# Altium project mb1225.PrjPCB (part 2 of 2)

## Sheet USB_OTG_HS.SchDoc: USB OTG HS PHY with micro A-B connector
size A4; Date: 29-OCT-2015; Author: A.B; CompanyName: STMicroelectronics; Organization: MCD/TOOLS/GNB; Address1: 12, Rue Jules HOROWITZ; Address2: 38019 Grenoble; Address3: FRANCE; DocumentNumber: MB1225; Revision: B-01; SheetNumber: 9; SheetTotal: 13; Project: STM32F769I-DISCO
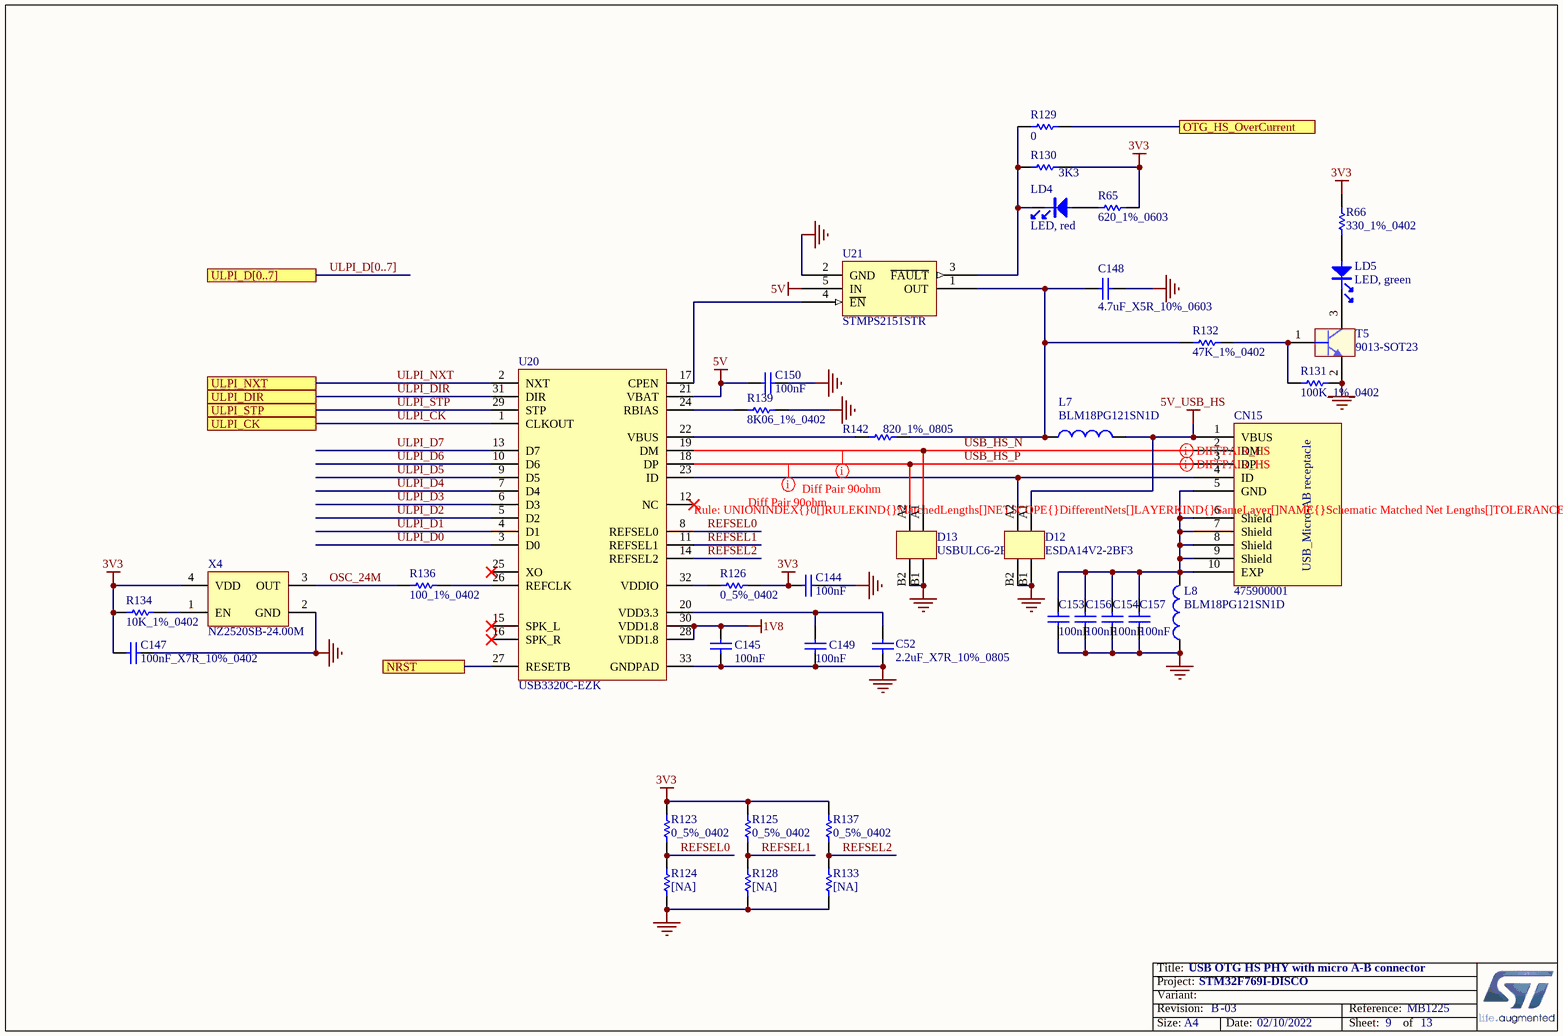
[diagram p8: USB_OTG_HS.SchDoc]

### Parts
C52  2.2uF_X7R_10%_0805  [TAN-A]
C144  100nF  [0402C]
C145  100nF  [0402C]
C147  100nF_X7R_10%_0402  [0402C]
C148  4.7uF_X5R_10%_0603  [0603C]
C149  100nF  [0402C]
C150  100nF  [0402C]
C153  100nF  [0402C]
C154  100nF  [0402C]
C156  100nF  [0402C]
C157  100nF  [0402C]
CN15  475900001  [MOLEX_47590001]
D12  ESDA14V2-2BF3  [BGA4_0R4_0R8X0R8]
D13  USBULC6-2F3  [BGA4_0R4_0R8X0R8]
L7  BLM18PG121SN1D  [0603L]
L8  BLM18PG121SN1D  [0603L]
LD4  LED, red  [0603D]
LD5  LED, green  [0603D]
R65  620_1%_0603  [0603R]
R66  330_1%_0402  [0402R]
R123  0_5%_0402  [0402R]
R124  [NA]  [0402R]
R125  0_5%_0402  [0402R]
R126  0_5%_0402  [0402R]
R128  [NA]  [0402R]
R129  0  [0402R]
R130  3K3  [0402R]
R131  100K_1%_0402  [0402R]
R132  47K_1%_0402  [0402R]
R133  [NA]  [0402R]
R134  10K_1%_0402  [0402R]
R136  100_1%_0402  [0402R]
R137  0_5%_0402  [0402R]
R139  8K06_1%_0402  [0402R]
R142  820_1%_0805  [0805R]
T5  9013-SOT23  [SOT-23]
U20  USB3320C-EZK  [QFN32_0R5_5X5]
U21  STMPS2151STR  [SOT23-5]
X4  NZ2520SB-24.00M  [OSC_4SM_2R5X2]

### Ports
NRST, OTG_HS_OverCurrent, ULPI_CK, ULPI_D[0..7], ULPI_DIR, ULPI_NXT, ULPI_STP

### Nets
1V8: C145.2 U20.28(VDD1.8) U20.30(VDD1.8)
3V3: C144.1 C147.1 R65.2 R66.2 R123.2 R125.2 R126.2 R130.1 R134.1 R137.2 X4.4(VDD)
5V: C150.1 U20.21(VBAT) U21.5(IN)
5V_USB_HS: CN15.1(VBUS) D12.A1 L7.2
GND: C52.1 C144.2 C145.1 C147.2 C148.2 C149.1 C150.2 C153.1 C154.1 C156.1 C157.1 D12.B1 D12.B2 D13.B1 D13.B2 L8.1 R124.1 R128.1 R131.2 R133.1 R139.2 T5.2(E) U20.33(GNDPAD) U21.2(GND) X4.2(GND)  [project net POE7]
NRST: U20.27(RESETB) ; port NRST
OSC_24M: R136.1 X4.3(OUT)
OTG_HS_OverCurrent: R129.2 ; port OTG_HS_OverCurrent
REFSEL0: R123.1 R124.2 U20.8(REFSEL0)
REFSEL1: R125.1 R128.2 U20.11(REFSEL1)
REFSEL2: R133.2 R137.1 U20.14(REFSEL2)
ULPI_CK: U20.1(CLKOUT) ; port ULPI_CK  [project net PA5]
ULPI_D0: U20.3(D0)  [project net PA3]
ULPI_D1: U20.4(D1)  [project net PB0]
ULPI_D2: U20.5(D2)  [project net PB1]
ULPI_D3: U20.6(D3)  [project net PB10]
ULPI_D4: U20.7(D4)  [project net PB11]
ULPI_D5: U20.9(D5)  [project net PB12]
ULPI_D6: U20.10(D6)  [project net PB13]
ULPI_D7: U20.13(D7)  [project net PB5]
ULPI_DIR: U20.31(DIR) ; port ULPI_DIR  [project net PI11]
ULPI_NXT: U20.2(NXT) ; port ULPI_NXT  [project net PH4]
ULPI_STP: U20.29(STP) ; port ULPI_STP  [project net PC0]
USB_HS_N: CN15.2(DM) D13.A1 U20.19(DM)
USB_HS_P: CN15.3(DP) D13.A2 U20.18(DP)
NetC52_2: C52.2 C149.2 U20.20(VDD3.3)
NetC148_1: C148.1 L7.1 R132.1 R142.2 U21.1(OUT)
NetC153_2: C153.2 C154.2 C156.2 C157.2 CN15.5(GND) CN15.6(Shield) CN15.7(Shield) CN15.8(Shield) CN15.9(Shield) CN15.10(EXP) L8.2
NetCN15_4: CN15.4(ID) D12.A2 U20.23(ID)
NetLD4_1: LD4.1 R65.1
NetLD4_2: LD4.2 R129.1 R130.2 U21.3(~{FAULT})
NetLD5_1: LD5.1 R66.1
NetLD5_2: LD5.2 T5.3(C)
NetR126_1: R126.1 U20.32(VDDIO)
NetR131_1: R131.1 R132.2 T5.1(B)
NetR134_2: R134.2 X4.1(EN)
NetR136_2: R136.2 U20.26(REFCLK)
NetR139_1: R139.1 U20.24(RBIAS)
NetR142_1: R142.1 U20.22(VBUS)
NetU20_17: U20.17(CPEN) U21.4(~{EN})

Not connected (* = marked no-connect by the designer): U20 12(NC)* 15(SPK_L)* 16(SPK_R)* 25(XO)*

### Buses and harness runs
bus ULPI_D[0..7] = port ULPI_D[0..7]

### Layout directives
differential pair: USB_HS_N, USB_HS_P
rule Matched Net Lengths [Tolerance = 150mil]: USB_HS_N, USB_HS_P

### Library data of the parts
C52 = Cap_2.2uF_X7R_10%_0805: Capacitor,2.2uF,16V, X7R,10%,0805,YAGEO; Manuf_Part_1: CC0805KKX7R7BB225
C144 C145 C147 C149 C150 C153 C154 C156 C157 = Cap_100nF_X7R_10%_0402: Capacitor,100nF,16V,X7R,10%,0402,YAGEO; Manuf_Part_1: CC0402KRX7R7BB104
C148 = Cap_4.7uF_X5R_10%_0603: Capacitor,4.7uF,16V, X5R,10%,0603,YAGEO; Manuf_Part_1: CC0603KRX5R7BB475; Order: CC0603KRX5R7BB105
CN15 = 475900001: USB-MICRO-AB, 47590-0001, SMT, MOLEX
D12 = ESDA14V2-2BF3: Quad bidirectional Transil array for ESD protection; Manuf_1: STM; ECCN_US/EU: EAR99/NEC; Provided: ST; Ref St: 9179040
D13 = USBULC6-2F3: 2-line Transil, (TVS), ultralow capacitance protection for high speed USB; Manuf_1: STM; ECCN_US/EU: EAR99/NEC; Ref St: 9151090; Provided: ST
L7 L8 = BEAD_120R_2A_0603: Bead,120R,2A,0603,BLM18PG121SN1D,MURATA; Manuf_Part_3: FCM1608KF-601T03; Manuf_2: TDK; Manuf_Part_2: MPZ1608S300A; Manuf_3: Tai-tech; Value: 100uH; Description_3: Bead,600R,350mA,0603,FCM1608KF-601T03,Tai-tech; Description_2: Bead,30R,5A,0603,MPZ1608S300A,TDK
LD4 = LED_red: LED, red, 0603; Manuf_1: everlight; Manuf_Part_1: 19-213-R6C-AP1Q2B/3T; ECCN_US/EU: EAR99/NEC
LD5 = LED_green: LED, green, 0603; Manuf_1: everlight; Manuf_Part_1: 19-213SYGC/S530-E2/TR8; ECCN_US/EU: EAR99/NEC
R65 = Res_620_1%_0603: Resistor,620,0603,1%,VISHAY; Manuf_Part_1: CRCW0603620RFKEA; Manuf_1: VISHAY DRALORIC; Value: 620; Order: 2122341
R66 = Res_330_1%_0402: Resistor,330,0402,1%,YAGEO; Manuf_Part_1: RC0402FR-07330RL; Value: 330
R123 R125 R126 R137 = Res_0_5%_0402: Resistor,0,0402,5%,YAGEO; Manuf_Part_1: RC0402JR-070RL; Value: 0; Order: 2363467
R124 R128 R133 = Res_NA_0402: Resistor,[NA],0402; Fitted: NO
R129 = Res_0_5%_0402: Resistor,0,0402,5%,YAGEO; Manuf_Part_1: RC0402JR-070RL; Order: 2363467
R130 = Res_3K3_1%_0402: Resistor,3K3,0402,1%,YAGEO; Manuf_Part_1: RC0402FR-073K3L
R131 = Res_100K_1%_0402: Resistor,100K,0402,1%,YAGEO; Manuf_Part_1: RC0402FR-07100KL; Manuf_Part_2: RT0402FRE07100KL
R132 = Res_47K_1%_0402: Resistor,47K,0402,1%,YAGEO; Manuf_Part_1: RC0402FR-0747KL; Order: 9239430
R134 = Res_10K_1%_0402: Resistor,10K,0402,1%,YAGEO; Manuf_Part_1: RC0402FR-0710KL
R136 = Res_100_1%_0402: Resistor,100,0402,1%,YAGEO; Manuf_Part_1: RC0402FR-07100RL; Value: 100; Order: 9239111
R139 = Res_8K06_1%_0402: Resistor,8K06,0402,1%,YAGEO; Manuf_Part_1: RC0402FR-078K06L
R142 = Res_820_1%_0805: Resistor,820,0805,1%,YAGEO; Manuf_Part_1: RC0805FR-07820RL; Value: 820
T5 = 9013-SOT23: NPN Bipolar Transistor; Manuf_1: NXP; Manuf_Part_1: BSR14; Order: 1081310; ECCN_US/EU: EAR99/NEC
U20 = USB3320C-EZK: USB3320C,  Hi-Speed USB Host, Device or OTG PHY with ULPI Low Pin Interface; Manuf_1: MICROCHIP; Manuf_Part_1: USB3320C-EZK-TR; ECCN_US/EU: EAR99/NEC; Provided: Sub Co
U21 = STMPS2151STR: Enhanced single channel power switches; Manuf_1: STM; Provided: ST; ECCN_US/EU: EAR99/NEC; Ref St: xxxxxx
X4 = OSC_24M_NZ2520SB: Oscillator 24.00Mhz, -+50PPM, 3.3V, Temp -55 to +125°C; Manuf_Part_2: KC2520B24.0000C10E00; Manuf_1: NDK; Manuf_Part_1: NZ2520SB 24MHz END4869A; Manuf_2: AVX Corp/Kyocera Corp; ECCN_US/EU: EAR99/NEC; Ref St: 9157032; Provided: ST

## Sheet STM32F7.SchDoc: STM32F769NIH6 Connexion
size A3; Date: 29-OCT-2015; Author: A.B; CompanyName: STMicroelectronics; Organization: MCD/TOOLS/GNB; Address1: 12, Rue Jules HOROWITZ; Address2: 38019 Grenoble; Address3: FRANCE; DocumentNumber: MB1225; Revision: B-01; SheetNumber: 4; SheetTotal: 13; Project: STM32F769I-DISCO
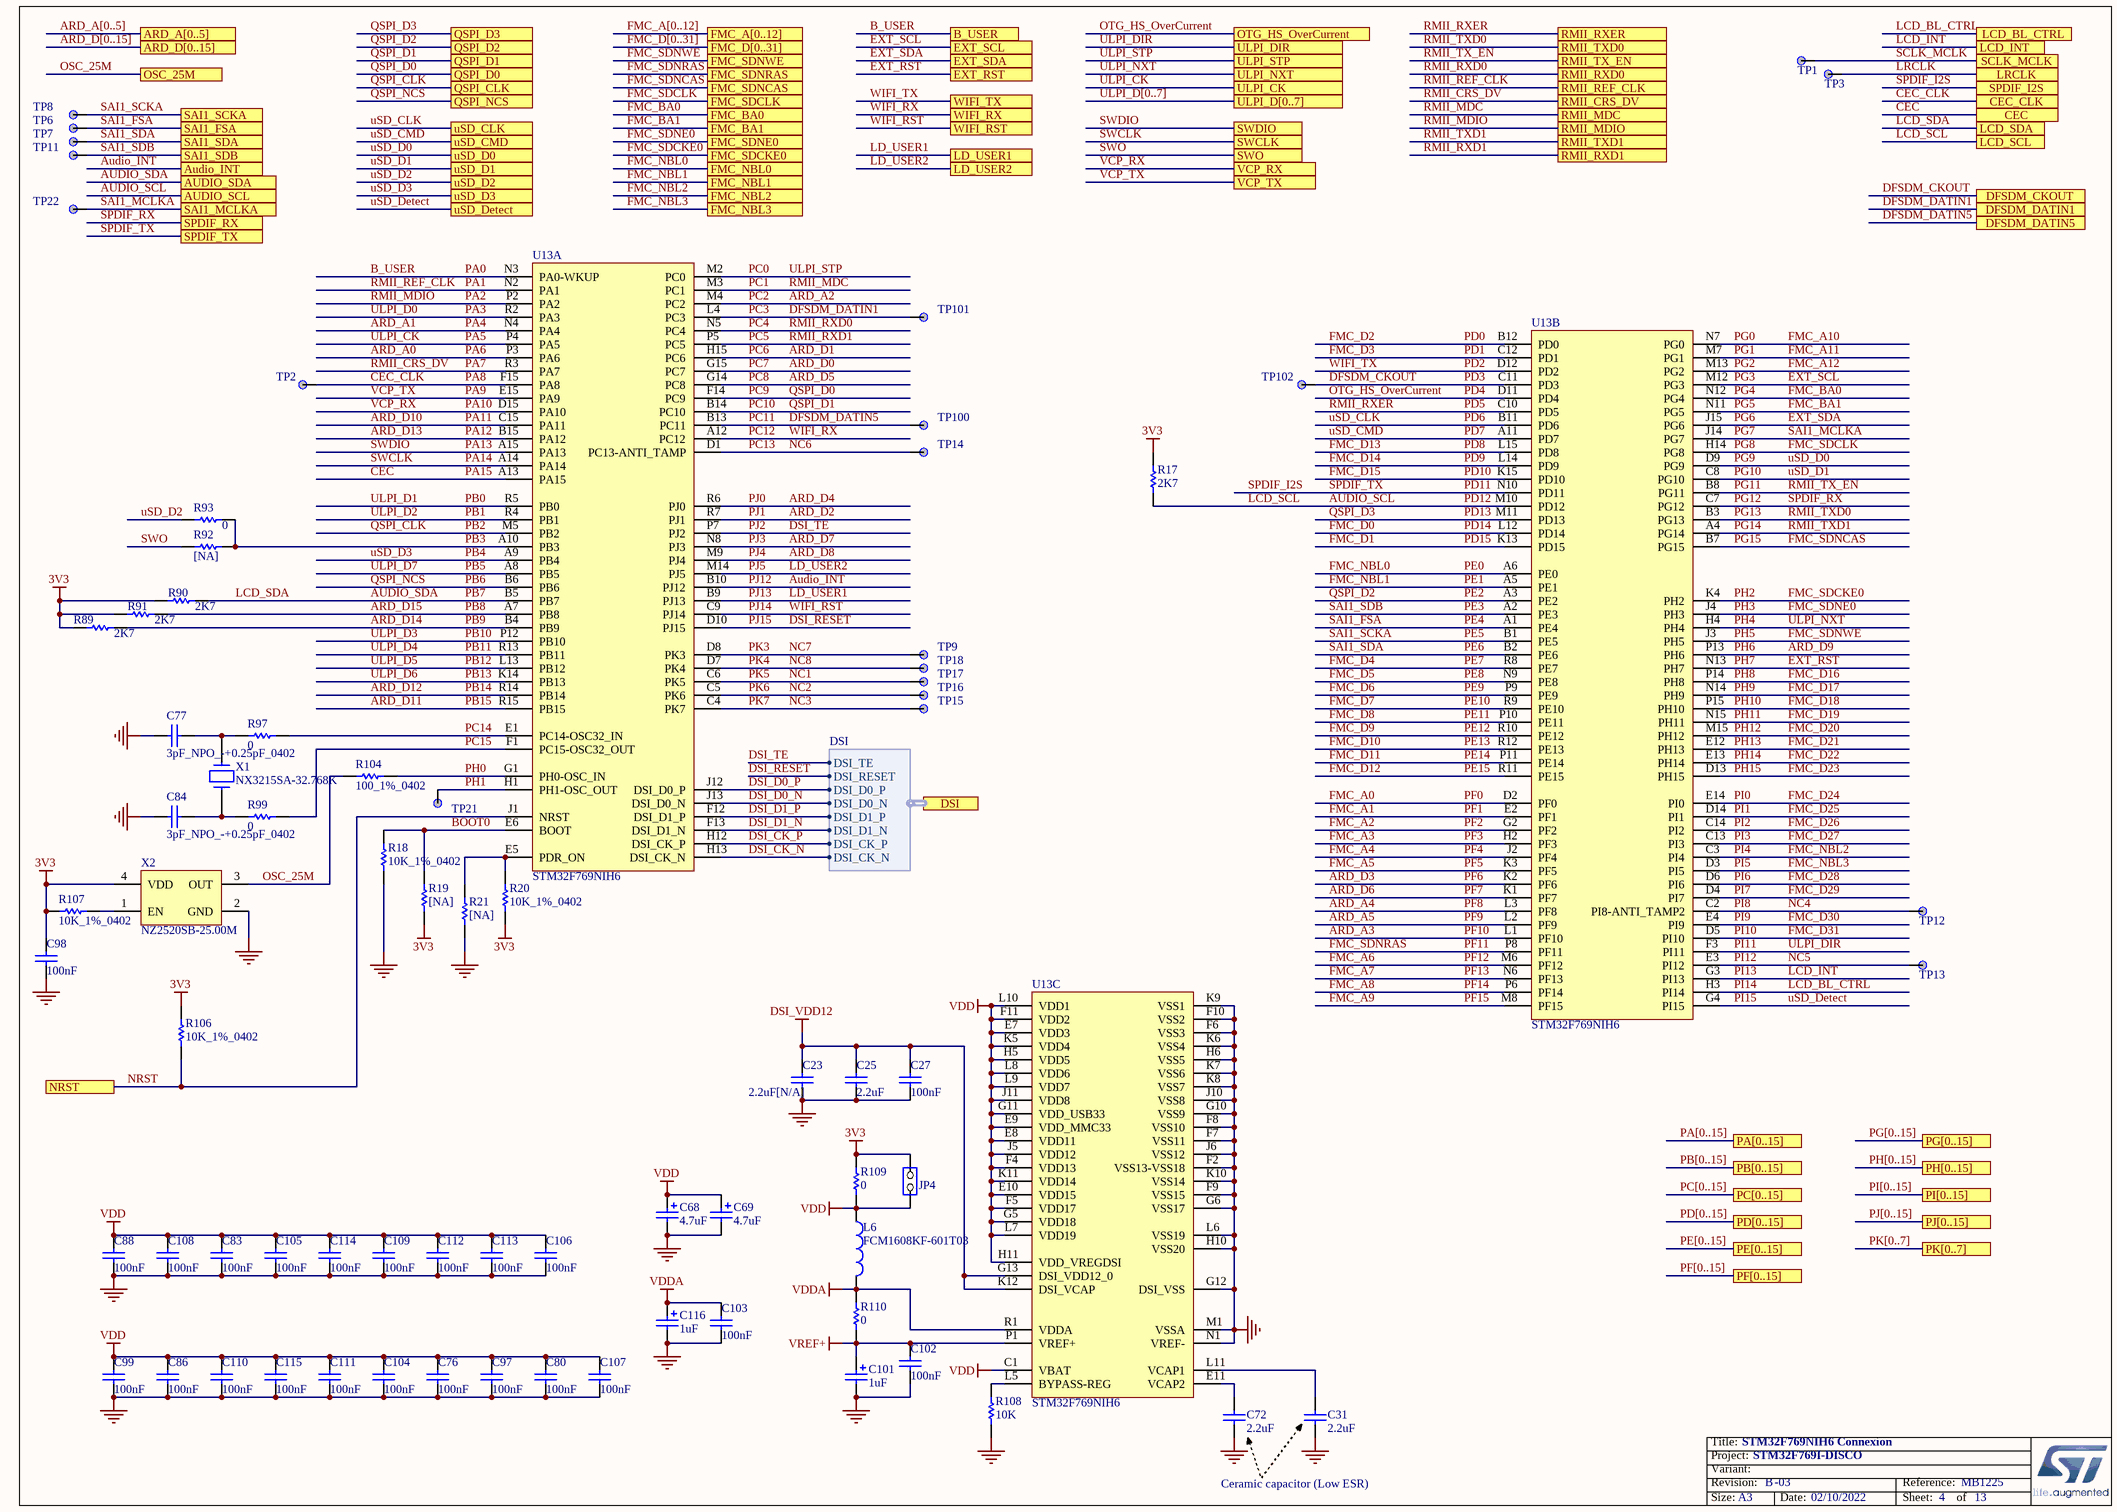
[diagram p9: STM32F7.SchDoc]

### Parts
C23  2.2uF[N/A]  [1206C]
C25  2.2uF  [0603C]
C27  100nF  [0402C]
C31  2.2uF  [1206C]
C68  4.7uF  [TAN-A]
C69  4.7uF  [TAN-A]
C72  2.2uF  [1206C]
C76  100nF  [0402C]
C77  3pF_NPO_-+0.25pF_0402  [0402C]
C80  100nF  [0402C]
C83  100nF  [0402C]
C84  3pF_NPO_-+0.25pF_0402  [0402C]
C86  100nF  [0402C]
C88  100nF  [0402C]
C97  100nF  [0402C]
C98  100nF  [0402C]
C99  100nF  [0402C]
C101  1uF  [TAN-A]
C102  100nF  [0402C]
C103  100nF  [0402C]
C104  100nF  [0402C]
C105  100nF  [0402C]
C106  100nF  [0402C]
C107  100nF  [0402C]
C108  100nF  [0402C]
C109  100nF  [0402C]
C110  100nF  [0402C]
C111  100nF  [0402C]
C112  100nF  [0402C]
C113  100nF  [0402C]
C114  100nF  [0402C]
C115  100nF  [0402C]
C116  1uF  [TAN-A]
JP4  JP2  [SIP2]  (value not drawn)
L6  FCM1608KF-601T03  [0603L]
R17  2K7  [0402R]
R18  10K_1%_0402  [0402R]
R19  [NA]  [0402R]
R20  10K_1%_0402  [0402R]
R21  [NA]  [0402R]
R89  2K7  [0402R]
R90  2K7  [0402R]
R91  2K7  [0402R]
R92  [NA]  [0402R]
R93  0  [0402R]
R97  0  [0402R]
R99  0  [0402R]
R104  100_1%_0402  [0402R]
R106  10K_1%_0402  [0402R]
R107  10K_1%_0402  [0402R]
R108  10K  [0402R]
R109  0  [0603R-GS]
R110  0  [0603R-GS]
TP1  TP  [TP_C40]  (value not drawn)
TP2  TP  [TP_C40]  (value not drawn)
TP3  TP  [TP_C40]  (value not drawn)
TP6  TP  [TP_C40]  (value not drawn)
TP7  TP  [TP_C40]  (value not drawn)
TP8  TP  [TP_C40]  (value not drawn)
TP9  TP  [TP_C40]  (value not drawn)
TP11  TP  [TP_C40]  (value not drawn)
TP12  TP  [TP_C40]  (value not drawn)
TP13  TP  [TP_C40]  (value not drawn)
TP14  TP  [TP_C40]  (value not drawn)
TP15  TP  [TP_C40]  (value not drawn)
TP16  TP  [TP_C40]  (value not drawn)
TP17  TP  [TP_C40]  (value not drawn)
TP18  TP  [TP_C40]  (value not drawn)
TP21  TP  [TP_C40]  (value not drawn)
TP22  TP  [TP_C40]  (value not drawn)
TP100  TP  [TP_C40]  (value not drawn)
TP101  TP  [TP_C40]  (value not drawn)
TP102  TP  [TP_C40]  (value not drawn)
U13  STM32F769NIH6  [BGA216_0R8_13X13]  (parts A,B,C of 3)
X1  NX3215SA-32.768K  [XTAL_2SM_3R2X1R5]
X2  NZ2520SB-25.00M  [OSC_4SM_2R5X2]

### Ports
ARD_A[0..5], ARD_D[0..15], Audio_INT, AUDIO_SCL, AUDIO_SDA, B_USER, CEC, CEC_CLK, DFSDM_CKOUT, DFSDM_DATIN1, DFSDM_DATIN5, DSI (harness DSI), EXT_RST, EXT_SCL, EXT_SDA, FMC_A[0..12], FMC_BA0, FMC_BA1, FMC_D[0..31], FMC_NBL0, FMC_NBL1, FMC_NBL2, FMC_NBL3, FMC_SDCKE0, FMC_SDCLK, FMC_SDNCAS, FMC_SDNE0, FMC_SDNRAS, FMC_SDNWE, LCD_BL_CTRL, LCD_INT, LCD_SCL, LCD_SDA, LD_USER1, LD_USER2, LRCLK, NRST, OSC_25M, OTG_HS_OverCurrent, PA[0..15], PB[0..15], PC[0..15], PD[0..15], PE[0..15], PF[0..15], PG[0..15], PH[0..15], PI[0..15], PJ[0..15], PK[0..7], QSPI_CLK, QSPI_D0, QSPI_D1, QSPI_D2, QSPI_D3, QSPI_NCS, RMII_CRS_DV, RMII_MDC, RMII_MDIO, RMII_REF_CLK, RMII_RXD0, RMII_RXD1, RMII_RXER, RMII_TX_EN, RMII_TXD0, RMII_TXD1, SAI1_FSA, SAI1_MCLKA, SAI1_SCKA, SAI1_SDA, SAI1_SDB, SCLK_MCLK, SPDIF_I2S, SPDIF_RX, SPDIF_TX, SWCLK, SWDIO, SWO, ULPI_CK, ULPI_D[0..7], ULPI_DIR, ULPI_NXT, ULPI_STP, uSD_CLK, uSD_CMD, uSD_D0, uSD_D1, uSD_D2, uSD_D3, uSD_Detect, VCP_RX, VCP_TX, WIFI_RST, WIFI_RX, WIFI_TX

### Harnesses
DSI: DSI_CK_P, DSI_CK_N, DSI_D0_P, DSI_D0_N, DSI_D1_P, DSI_D1_N, DSI_TE, DSI_RESET

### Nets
3V3: C98.2 JP4.2(NO) R17.2 R19.1 R20.1 R89.1 R90.1 R91.1 R106.2 R107.1 R109.2 X2.4(VDD)
DSI_VDD12: C23.2 C25.2 C27.2 U13.G13(DSI_VDD12_0) U13.K12(DSI_VCAP)
GND: C23.1 C25.1 C27.1 C31.1 C68.2 C69.2 C72.1 C76.1 C77.1 C80.1 C83.1 C84.1 C86.1 C88.1 C97.1 C98.1 C99.1 C101.2 C102.1 C103.1 C104.1 C105.1 C106.1 C107.1 C108.1 C109.1 C110.1 C111.1 C112.1 C113.1 C114.1 C115.1 C116.2 R18.1 R21.1 R108.1 U13.F2(VSS13-VSS18) U13.F6(VSS3) U13.F7(VSS11) U13.F8(VSS10) U13.F9(VSS15) U13.F10(VSS2) U13.G6(VSS17) U13.G10(VSS9) U13.G12(DSI_VSS) U13.H6(VSS5) U13.H10(VSS20) U13.J6(VSS12) U13.J10(VSS8) U13.K6(VSS4) U13.K7(VSS6) U13.K8(VSS7) U13.K9(VSS1) U13.K10(VSS14) U13.L6(VSS19) U13.M1(VSSA) U13.N1(VREF-) X2.2(GND)  [project net POE7]
VDD: C68.1 C69.1 C76.2 C80.2 C83.2 C86.2 C88.2 C97.2 C99.2 C104.2 C105.2 C106.2 C107.2 C108.2 C109.2 C110.2 C111.2 C112.2 C113.2 C114.2 C115.2 JP4.1(COMMON) L6.1 R109.1 U13.C1(VBAT) U13.E7(VDD3) U13.E8(VDD11) U13.E9(VDD_MMC33) U13.E10(VDD15) U13.F4(VDD13) U13.F5(VDD17) U13.F11(VDD2) U13.G5(VDD18) U13.G11(VDD_USB33) U13.H5(VDD5) U13.H11(VDD_VREGDSI) U13.J5(VDD12) U13.J11(VDD8) U13.K5(VDD4) U13.K11(VDD14) U13.L7(VDD19) U13.L8(VDD6) U13.L9(VDD7) U13.L10(VDD1)
VDDA: C103.2 C116.1 L6.2 R110.1 U13.R1(VDDA)
VREF+: C101.1 C102.2 R110.2 U13.P1(VREF+)
ARD_A0: U13.P3(PA6)  [also labelled PA6]
ARD_A1: U13.N4(PA4)  [also labelled PA4]
ARD_A2: U13.M4(PC2)  [also labelled PC2]
ARD_A3: U13.L1(PF10)  [also labelled PF10]
ARD_A4: U13.L3(PF8)  [also labelled PF8]
ARD_A5: U13.L2(PF9)  [also labelled PF9]
ARD_D0: U13.G15(PC7)  [also labelled PC7]
ARD_D1: U13.H15(PC6)  [also labelled PC6]
ARD_D2: U13.R7(PJ1)  [also labelled PJ1]
ARD_D3: U13.K2(PF6)  [also labelled PF6]
ARD_D4: U13.R6(PJ0)  [also labelled PJ0]
ARD_D5: U13.G14(PC8)  [also labelled PC8]
ARD_D6: U13.K1(PF7)  [also labelled PF7]
ARD_D7: U13.N8(PJ3)  [also labelled PJ3]
ARD_D8: U13.M9(PJ4)  [also labelled PJ4]
ARD_D9: U13.P13(PH6)  [also labelled PH6]
ARD_D10: U13.C15(PA11)  [also labelled PA11]
ARD_D11: U13.R15(PB15)  [also labelled PB15]
ARD_D12: U13.R14(PB14)  [also labelled PB14]
ARD_D13: U13.B15(PA12)  [also labelled PA12]
ARD_D14: R89.2 U13.B4(PB9)  [also labelled PB9]
ARD_D15: R91.2 U13.A7(PB8)  [also labelled PB8]
Audio_INT: U13.B10(PJ12) ; port Audio_INT  [also labelled PJ12]
AUDIO_SCL: R17.1 U13.M10(PD12) ; port AUDIO_SCL, port LCD_SCL  [also labelled LCD_SCL, PD12]
AUDIO_SDA: R90.2 U13.B5(PB7) ; port AUDIO_SDA, port LCD_SDA  [also labelled LCD_SDA, PB7]
B_USER: U13.N3(PA0-WKUP) ; port B_USER  [also labelled PA0]
BOOT0: R18.2 R19.2 U13.E6(BOOT)
CEC: U13.A13(PA15) ; port CEC  [also labelled PA15]
CEC_CLK: TP2.1 U13.F15(PA8) ; port CEC_CLK  [also labelled PA8]
DFSDM_CKOUT: TP102.1 U13.C11(PD3) ; port DFSDM_CKOUT  [also labelled PD3]
DFSDM_DATIN1: TP101.1 U13.L4(PC3) ; port DFSDM_DATIN1  [also labelled PC3]
DFSDM_DATIN5: TP100.1 U13.B13(PC11) ; port DFSDM_DATIN5  [also labelled PC11]
DSI_CK_N: U13.H13(DSI_CK_N) ; port DSI.DSI_CK_N
DSI_CK_P: U13.H12(DSI_CK_P) ; port DSI.DSI_CK_P
DSI_D0_N: U13.J13(DSI_D0_N) ; port DSI.DSI_D0_N
DSI_D0_P: U13.J12(DSI_D0_P) ; port DSI.DSI_D0_P
DSI_D1_N: U13.F13(DSI_D1_N) ; port DSI.DSI_D1_N
DSI_D1_P: U13.F12(DSI_D1_P) ; port DSI.DSI_D1_P
DSI_RESET: U13.D10(PJ15) ; port DSI.DSI_RESET  [also labelled PJ15]
DSI_TE: U13.P7(PJ2) ; port DSI.DSI_TE  [also labelled PJ2]
EXT_RST: U13.N13(PH7) ; port EXT_RST  [also labelled PH7]
EXT_SCL: U13.M12(PG3) ; port EXT_SCL  [also labelled PG3]
EXT_SDA: U13.J15(PG6) ; port EXT_SDA  [also labelled PG6]
FMC_A0: U13.D2(PF0)  [also labelled PF0]
FMC_A1: U13.E2(PF1)  [also labelled PF1]
FMC_A2: U13.G2(PF2)  [also labelled PF2]
FMC_A3: U13.H2(PF3)  [also labelled PF3]
FMC_A4: U13.J2(PF4)  [also labelled PF4]
FMC_A5: U13.K3(PF5)  [also labelled PF5]
FMC_A6: U13.M6(PF12)  [also labelled PF12]
FMC_A7: U13.N6(PF13)  [also labelled PF13]
FMC_A8: U13.P6(PF14)  [also labelled PF14]
FMC_A9: U13.M8(PF15)  [also labelled PF15]
FMC_A10: U13.N7(PG0)  [also labelled PG0]
FMC_A11: U13.M7(PG1)  [also labelled PG1]
FMC_A12: U13.M13(PG2)  [also labelled PG2]
FMC_BA0: U13.N12(PG4) ; port FMC_BA0  [also labelled PG4]
FMC_BA1: U13.N11(PG5) ; port FMC_BA1  [also labelled PG5]
FMC_D0: U13.L12(PD14)  [also labelled PD14]
FMC_D1: U13.K13(PD15)  [also labelled PD15]
FMC_D2: U13.B12(PD0)  [also labelled PD0]
FMC_D3: U13.C12(PD1)  [also labelled PD1]
FMC_D4: U13.R8(PE7)  [also labelled PE7]
FMC_D5: U13.N9(PE8)  [also labelled PE8]
FMC_D6: U13.P9(PE9)  [also labelled PE9]
FMC_D7: U13.R9(PE10)  [also labelled PE10]
FMC_D8: U13.P10(PE11)  [also labelled PE11]
FMC_D9: U13.R10(PE12)  [also labelled PE12]
FMC_D10: U13.R12(PE13)  [also labelled PE13]
FMC_D11: U13.P11(PE14)  [also labelled PE14]
FMC_D12: U13.R11(PE15)  [also labelled PE15]
FMC_D13: U13.L15(PD8)  [also labelled PD8]
FMC_D14: U13.L14(PD9)  [also labelled PD9]
FMC_D15: U13.K15(PD10)  [also labelled PD10]
FMC_D16: U13.P14(PH8)  [also labelled PH8]
FMC_D17: U13.N14(PH9)  [also labelled PH9]
FMC_D18: U13.P15(PH10)  [also labelled PH10]
FMC_D19: U13.N15(PH11)  [also labelled PH11]
FMC_D20: U13.M15(PH12)  [also labelled PH12]
FMC_D21: U13.E12(PH13)  [also labelled PH13]
FMC_D22: U13.E13(PH14)  [also labelled PH14]
FMC_D23: U13.D13(PH15)  [also labelled PH15]
FMC_D24: U13.E14(PI0)  [also labelled PI0]
FMC_D25: U13.D14(PI1)  [also labelled PI1]
FMC_D26: U13.C14(PI2)  [also labelled PI2]
FMC_D27: U13.C13(PI3)  [also labelled PI3]
FMC_D28: U13.D6(PI6)  [also labelled PI6]
FMC_D29: U13.D4(PI7)  [also labelled PI7]
FMC_D30: U13.E4(PI9)  [also labelled PI9]
FMC_D31: U13.D5(PI10)  [also labelled PI10]
FMC_NBL0: U13.A6(PE0) ; port FMC_NBL0  [also labelled PE0]
FMC_NBL1: U13.A5(PE1) ; port FMC_NBL1  [also labelled PE1]
FMC_NBL2: U13.C3(PI4) ; port FMC_NBL2  [also labelled PI4]
FMC_NBL3: U13.D3(PI5) ; port FMC_NBL3  [also labelled PI5]
FMC_SDCKE0: U13.K4(PH2) ; port FMC_SDCKE0  [also labelled PH2]
FMC_SDCLK: U13.H14(PG8) ; port FMC_SDCLK  [also labelled PG8]
FMC_SDNCAS: U13.B7(PG15) ; port FMC_SDNCAS  [also labelled PG15]
FMC_SDNE0: U13.J4(PH3) ; port FMC_SDNE0  [also labelled PH3]
FMC_SDNRAS: U13.P8(PF11) ; port FMC_SDNRAS  [also labelled PF11]
FMC_SDNWE: U13.J3(PH5) ; port FMC_SDNWE  [also labelled PH5]
LCD_BL_CTRL: U13.H3(PI14) ; port LCD_BL_CTRL  [also labelled PI14]
LCD_INT: U13.G3(PI13) ; port LCD_INT  [also labelled PI13]
LD_USER1: U13.B9(PJ13) ; port LD_USER1  [also labelled PJ13]
LD_USER2: U13.M14(PJ5) ; port LD_USER2  [also labelled PJ5]
LRCLK: TP3.1 ; port LRCLK
NC1: TP17.1 U13.C6(PK5)  [also labelled PK5]
NC2: TP16.1 U13.C5(PK6)  [also labelled PK6]
NC3: TP15.1 U13.C4(PK7)  [also labelled PK7]
NC4: TP12.1 U13.C2(PI8-ANTI_TAMP2)  [also labelled PI8]
NC5: TP13.1 U13.E3(PI12)  [also labelled PI12]
NC6: TP14.1 U13.D1(PC13-ANTI_TAMP)  [also labelled PC13]
NC7: TP9.1 U13.D8(PK3)  [also labelled PK3]
NC8: TP18.1 U13.D7(PK4)  [also labelled PK4]
NRST: R106.1 U13.J1(NRST) ; port NRST
OSC_25M: R104.1 X2.3(OUT) ; port OSC_25M
OTG_HS_OverCurrent: U13.D11(PD4) ; port OTG_HS_OverCurrent  [also labelled PD4]
PA1: U13.N2(PA1) ; port RMII_REF_CLK  [also labelled RMII_REF_CLK]
PA2: U13.P2(PA2) ; port RMII_MDIO  [also labelled RMII_MDIO]
PA3: U13.R2(PA3)  [also labelled ULPI_D0]
PA5: U13.P4(PA5) ; port ULPI_CK  [also labelled ULPI_CK]
PA7: U13.R3(PA7) ; port RMII_CRS_DV  [also labelled RMII_CRS_DV]
PA9: U13.E15(PA9) ; port VCP_TX  [also labelled VCP_TX]
PA10: U13.D15(PA10) ; port VCP_RX  [also labelled VCP_RX]
PA13: U13.A15(PA13) ; port SWDIO  [also labelled SWDIO]
PA14: U13.A14(PA14) ; port SWCLK  [also labelled SWCLK]
PB0: U13.R5(PB0)  [also labelled ULPI_D1]
PB1: U13.R4(PB1)  [also labelled ULPI_D2]
PB2: U13.M5(PB2) ; port QSPI_CLK  [also labelled QSPI_CLK]
PB3: R92.2 R93.2 U13.A10(PB3)
PB4: U13.A9(PB4) ; port uSD_D3  [also labelled uSD_D3]
PB5: U13.A8(PB5)  [also labelled ULPI_D7]
PB6: U13.B6(PB6) ; port QSPI_NCS  [also labelled QSPI_NCS]
PB10: U13.P12(PB10)  [also labelled ULPI_D3]
PB11: U13.R13(PB11)  [also labelled ULPI_D4]
PB12: U13.L13(PB12)  [also labelled ULPI_D5]
PB13: U13.K14(PB13)  [also labelled ULPI_D6]
PC0: U13.M2(PC0) ; port ULPI_STP  [also labelled ULPI_STP]
PC1: U13.M3(PC1) ; port RMII_MDC  [also labelled RMII_MDC]
PC4: U13.N5(PC4) ; port RMII_RXD0  [also labelled RMII_RXD0]
PC5: U13.P5(PC5) ; port RMII_RXD1  [also labelled RMII_RXD1]
PC9: U13.F14(PC9) ; port QSPI_D0  [also labelled QSPI_D0]
PC10: U13.B14(PC10) ; port QSPI_D1  [also labelled QSPI_D1]
PC12: U13.A12(PC12) ; port WIFI_RX  [also labelled WIFI_RX]
PC14: R97.2 U13.E1(PC14-OSC32_IN)
PC15: R99.2 U13.F1(PC15-OSC32_OUT)
PD2: U13.D12(PD2) ; port WIFI_TX  [also labelled WIFI_TX]
PD5: U13.C10(PD5) ; port RMII_RXER  [also labelled RMII_RXER]
PD6: U13.B11(PD6) ; port uSD_CLK  [also labelled uSD_CLK]
PD7: U13.A11(PD7) ; port uSD_CMD  [also labelled uSD_CMD]
PD11: U13.N10(PD11) ; port SPDIF_TX, port SPDIF_I2S  [also labelled SPDIF_I2S, SPDIF_TX]
PD13: U13.M11(PD13) ; port QSPI_D3  [also labelled QSPI_D3]
PE2: U13.A3(PE2) ; port QSPI_D2  [also labelled QSPI_D2]
PE3: TP11.1 U13.A2(PE3) ; port SAI1_SDB  [also labelled SAI1_SDB]
PE4: TP6.1 U13.A1(PE4) ; port SAI1_FSA  [also labelled SAI1_FSA]
PE5: TP8.1 U13.B1(PE5) ; port SAI1_SCKA  [also labelled SAI1_SCKA]
PE6: TP7.1 U13.B2(PE6) ; port SAI1_SDA  [also labelled SAI1_SDA]
PG7: TP22.1 U13.J14(PG7) ; port SAI1_MCLKA  [also labelled SAI1_MCLKA]
PG9: U13.D9(PG9) ; port uSD_D0  [also labelled uSD_D0]
PG10: U13.C8(PG10) ; port uSD_D1  [also labelled uSD_D1]
PG11: U13.B8(PG11) ; port RMII_TX_EN  [also labelled RMII_TX_EN]
PG12: U13.C7(PG12) ; port SPDIF_RX  [also labelled SPDIF_RX]
PG13: U13.B3(PG13) ; port RMII_TXD0  [also labelled RMII_TXD0]
PG14: U13.A4(PG14) ; port RMII_TXD1  [also labelled RMII_TXD1]
PH0: R104.2 U13.G1(PH0-OSC_IN)
PH1: TP21.1 U13.H1(PH1-OSC_OUT)
PH4: U13.H4(PH4) ; port ULPI_NXT  [also labelled ULPI_NXT]
PI11: U13.F3(PI11) ; port ULPI_DIR  [also labelled ULPI_DIR]
PI15: U13.G4(PI15) ; port uSD_Detect  [also labelled uSD_Detect]
PJ14: U13.C9(PJ14) ; port WIFI_RST  [also labelled WIFI_RST]
SCLK_MCLK: TP1.1 ; port SCLK_MCLK
SWO: R92.1 ; port SWO
uSD_D2: R93.1 ; port uSD_D2
NetC31_2: C31.2 U13.L11(VCAP1)
NetC72_2: C72.2 U13.E11(VCAP2)
NetC77_2: C77.2 R97.1 X1.1
NetC84_2: C84.2 R99.1 X1.2
NetR20_2: R20.2 R21.2 U13.E5(PDR_ON)
NetR107_2: R107.2 X2.1(EN)
NetR108_2: R108.2 U13.L5(BYPASS-REG)

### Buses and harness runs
bus ARD_A[0..5] = port ARD_A[0..5]
bus ARD_D[0..15] = port ARD_D[0..15]
bus FMC_A[0..12] = port FMC_A[0..12]
bus FMC_D[0..31] = port FMC_D[0..31]
bus PA[0..15] = port PA[0..15]
bus PB[0..15] = port PB[0..15]
bus PC[0..15] = port PC[0..15]
bus PD[0..15] = port PD[0..15]
bus PE[0..15] = port PE[0..15]
bus PF[0..15] = port PF[0..15]
bus PG[0..15] = port PG[0..15]
bus PH[0..15] = port PH[0..15]
bus PI[0..15] = port PI[0..15]
bus PJ[0..15] = port PJ[0..15]
bus PK[0..7] = port PK[0..7]
bus ULPI_D[0..7] = port ULPI_D[0..7]

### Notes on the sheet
- Ceramic capacitor (Low ESR)

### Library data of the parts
C23 = Cap_2.2uF_X7R_10%_1206: Capacitor,2.2uF,16V, X7R,10%,1206,YAGEO; Manuf_Part_1: CC1206KKX7R7BB225; Manuf_Part_2: C1206C225K4RAC; Manuf_2: KEMET; Fitted: NO
C25 = Cap_2.2uF_X5R_10%_0603: Capacitor,2.2uF,10V, X5R,10%,0603,YAGEO; Manuf_Part_1: CC0603KRX5R6BB225; Manuf_Part_2: C0603C225K8PACTU; Manuf_2: KEMET
C27 C76 C80 C83 C86 C88 C97-C99 C102-C115 = Cap_100nF_X7R_10%_0402: as C144 on sheet USB_OTG_HS
C31 C72 = Cap_2.2uF_X7R_10%_1206: Capacitor,2.2uF,16V, X7R,10%,1206,YAGEO; Manuf_Part_1: CC1206KKX7R7BB225; Manuf_Part_2: C1206C225K4RAC; Manuf_2: KEMET
C68 C69 = Cap_4.7uF_POL_10%_TANA: Polarized Capacitor,4.7uF,16V,10%,typeA,AVX; Manuf_Part_1: TAJA475K016R
C77 C84 = Cap_4.3pF_NPO_-+0.25pF_0402: Capacitor, 3pF, 16V, NPO, -+0.25pF, 0402, KEMET; Manuf_1: AVX; Manuf_Part_1: C0402C439C4GACTU; Order: C0402C439C4GACTU-ND
C101 C116 = Cap_1uF_POL_10%_TANA: Polarized Capacitor,1uF,16V,10%,typeA,AVX; Manuf_Part_1: TAJA105K016R
JP4 = JP2: Fitted: NO
L6 = BEAD_600R_350MA_0603: Bead,600R,350mA,0603,FCM1608KF-601T03,Tai-tech; Manuf_2: TDK; Manuf_Part_2: MPZ1608S300A; Manuf_Part_3: BLM18PG121SN1D; Manuf_3: MURATA; Value: 100uH; Description_2: Bead,30R,5A,0603,MPZ1608S300A,TDK; Description_3: Bead,120R,2A,0603,BLM18PG121SN1D,MURATA
R17 R89-R91 = Res_2K7_1%_0402: Resistor,2K7,0402,1%,YAGEO; Manuf_Part_1: RC0402FR-072K7L
R18 R20 R106-R108 = Res_10K_1%_0402: as R134 on sheet USB_OTG_HS
R19 R21 R92 = Res_NA_0402: Resistor,[NA],0402; Fitted: NO
R93 R97 R99 = Res_0_5%_0402: as R129 on sheet USB_OTG_HS
R104 = Res_100_1%_0402: as R136 on sheet USB_OTG_HS
R109 R110 = Res_0_5%_0603: Resistor,0,0603,5%,YAGEO; Manuf_Part_1: RC0603JR-070RL; Order: 2363481
TP1-TP3 TP6-TP9 TP11-TP18 TP21 TP22 TP100-TP102 = TP: Test Point
U13 = STM32F769NIH6U: STM32F769NIH6 (STM32F7 Big Birdie) TBGA216; Manuf_1: STM; ECCN_US/EU: 3A991A2/NEC; Ref St: xxxxxxxx; Provided: ST
X1 = XTAL_32K_NX3215SA: Crystal 32.768kHz, 6pF, -+20PPM, R=50K, SMD; Manuf_1: NDK; Manuf_Part_1: NX3215SA 32.768KHz EXS00A-MU00525; ECCN_US/EU: EAR99/NEC; Ref St: 9157034; NDK Ref: X3101802; Provided: ST
X2 = OSC_25M_NZ2520SB: Oscillator 25.00Mhz, -+50PPM, 3.3V, Temp -55 to +125°C; Manuf_Part_1: NZ2520SB 25MHz END4869B; Manuf_1: NDK; Manuf_Part_2: KC2520B25.0000C10E00; Manuf_2: AVX Corp/Kyocera Corp; ECCN_US/EU: EAR99/NEC; Ref St: 9157031; Provided: ST

## Sheet Ethernet.SchDoc: Ethernet PHY with RJ45 connector
size A4; Date: 29-OCT-2015; Author: A.B; CompanyName: STMicroelectronics; Organization: MCD/TOOLS/GNB; Address1: 12, Rue Jules HOROWITZ; Address2: 38019 Grenoble; Address3: FRANCE; DocumentNumber: MB1225; Revision: B-01; SheetNumber: 10; SheetTotal: 13; Project: STM32F769I-DISCO
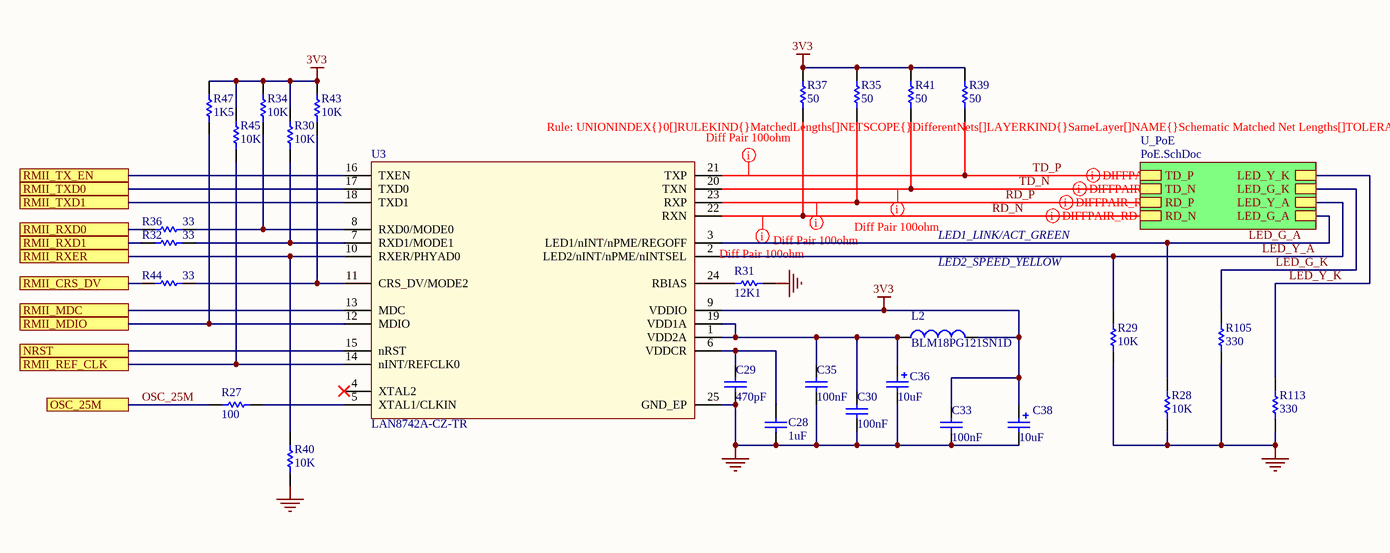
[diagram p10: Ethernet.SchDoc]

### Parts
C28  1uF  [0603C]
C29  470pF  [0402C]
C30  100nF  [0402C]
C33  100nF  [0402C]
C35  100nF  [0402C]
C36  10uF  [TAN-A]
C38  10uF  [TAN-A]
L2  BLM18PG121SN1D  [0603L]
R27  100  [0402R]
R28  10K  [0402R]
R29  10K  [0402R]
R30  10K  [0402R]
R31  12K1  [0603R]
R32  33  [0402R]
R34  10K  [0402R]
R35  50  [0402R]
R36  33  [0402R]
R37  50  [0402R]
R39  50  [0402R]
R40  10K  [0402R]
R41  50  [0402R]
R43  10K  [0402R]
R44  33  [0402R]
R45  10K  [0402R]
R47  1K5  [0402R]
R105  330  [0402R]
R113  330  [0402R]
U3  LAN8742A-CZ-TR  [QFN24_0R5_4X4]

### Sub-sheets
U_PoE = PoE.SchDoc: LED_G_A, LED_G_K, LED_Y_A, LED_Y_K, RD_P, TD_N, TD_P, RD_N

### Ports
NRST, OSC_25M, RMII_CRS_DV, RMII_MDC, RMII_MDIO, RMII_REF_CLK, RMII_RXD0, RMII_RXD1, RMII_RXER, RMII_TX_EN, RMII_TXD0, RMII_TXD1

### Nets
3V3: C33.2 C38.1 L2.2 R30.2 R34.2 R35.1 R37.1 R39.1 R41.1 R43.2 R45.2 R47.2 U3.9(VDDIO)
GND: C28.1 C29.1 C30.1 C33.1 C35.1 C36.2 C38.2 R28.1 R29.1 R31.2 R40.1 R105.1 R113.1 U3.25(GND_EP)  [project net POE7]
LED_G_A: R28.2 U3.3(LED1/nINT/nPME/REGOFF) ; sheet U_PoE/LED_G_A
LED_G_K: R105.2 ; sheet U_PoE/LED_G_K
LED_Y_A: R29.2 U3.2(LED2/nINT/nPME/nINTSEL) ; sheet U_PoE/LED_Y_A
LED_Y_K: R113.2 ; sheet U_PoE/LED_Y_K
NRST: U3.15(nRST) ; port NRST
OSC_25M: R27.1 ; port OSC_25M
PA1: R45.1 U3.14(nINT/REFCLK0) ; port RMII_REF_CLK
PA2: R47.1 U3.12(MDIO) ; port RMII_MDIO
PA7: R44.2 ; port RMII_CRS_DV
PC1: U3.13(MDC) ; port RMII_MDC
PC4: R36.2 ; port RMII_RXD0
PC5: R32.2 ; port RMII_RXD1
PD5: R40.2 U3.10(RXER/PHYAD0) ; port RMII_RXER
PG11: U3.16(TXEN) ; port RMII_TX_EN
PG13: U3.17(TXD0) ; port RMII_TXD0
PG14: U3.18(TXD1) ; port RMII_TXD1
RD_N: R37.2 U3.22(RXN) ; sheet U_PoE/RD_N
RD_P: R35.2 U3.23(RXP) ; sheet U_PoE/RD_P
TD_N: R41.2 U3.20(TXN) ; sheet U_PoE/TD_N
TD_P: R39.2 U3.21(TXP) ; sheet U_PoE/TD_P
NetC28_2: C28.2 C29.2 U3.6(VDDCR)
NetC30_2: C30.2 C35.2 C36.1 L2.1 U3.1(VDD2A) U3.19(VDD1A)
NetR27_2: R27.2 U3.5(XTAL1/CLKIN)
NetR30_1: R30.1 R32.1 U3.7(RXD1/MODE1)
NetR31_1: R31.1 U3.24(RBIAS)
NetR34_1: R34.1 R36.1 U3.8(RXD0/MODE0)
NetR43_1: R43.1 R44.1 U3.11(CRS_DV/MODE2)

Not connected (* = marked no-connect by the designer): U3 4(XTAL2)*

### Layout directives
differential pair: RD_N, RD_P, TD_N, TD_P
rule Matched Net Lengths [Tolerance = 100mil]: RD_N, RD_P, TD_N, TD_P

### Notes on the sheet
- LED2_SPEED_YELLOW
- LED1_LINK/ACT_GREEN

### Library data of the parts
C28 = Cap_1uF_X5R_10%_0603: Capacitor,1uF,16V,X5R,10%,0603,YAGEO; Manuf_Part_1: CC0603KRX5R7BB105
C29 = Cap_470pF_X7R_10%_0402: Capacitor,470pF,16V,X7R,10%,0402,YAGEO; Manuf_Part_1: 0402YC471KAT4A
C30 C33 C35 = Cap_100nF_X7R_10%_0402: as C144 on sheet USB_OTG_HS
C36 C38 = Cap_10uF_POL_10%_TANA: Polarized Capacitor,10uF,10V,10%,typeA,VISHAY; Manuf_Part_1: 293D106X9010A2TE3
L2 = BEAD_120R_2A_0603: as L7 on sheet USB_OTG_HS
R27 = Res_100_1%_0402: Resistor,100,0402,1%,YAGEO; Manuf_Part_1: RC0402FR-07100RL; Order: 9239111
R28-R30 R34 R40 R43 R45 = Res_10K_1%_0402: as R134 on sheet USB_OTG_HS
R31 = Res_12K1_1%_0603: Resistor,12K1,0603,1%,VISHAY; Manuf_Part_1: MCT 0603-50 1% P5 12K1; Order: 2325243
R32 R36 R44 = Res_33_1%_0402: Resistor,33,0402,1%,YAGEO; Manuf_Part_1: RC0402FR-0733RL
R35 R37 R39 R41 = Res_50_1%_0402: Resistor,50,0402,1%,YAGEO; Manuf_Part_1: RC0402FR-0750RL
R47 = Res_1K5_1%_0402: Resistor,1K5,0402,1%,YAGEO; Manuf_Part_1: RC0402FR-071K5L
R105 R113 = Res_330_1%_0402: Resistor,330,0402,1%,YAGEO; Manuf_Part_1: RC0402FR-07330RL
U3 = LAN8742A-CZ-TR: LAN8742A-CZ-TR - Small Footprint RMII 10/100 Ethernet, Transceiver with HP Auto-MDIX and flexPWR Technology SQFN-24; Manuf_1: MICROCHIP; ECCN_US/EU: EAR99/NEC; Provided: Sub Co

## Sheet PoE.SchDoc: Power Over Ethernet 3W
size A4; Date: 29-OCT-2015; Author: A.B; CompanyName: STMicroelectronics; Organization: MCD/TOOLS/GNB; Address1: 12, Rue Jules HOROWITZ; Address2: 38019 Grenoble; Address3: FRANCE; DocumentNumber: MB1225; Revision: B-01; SheetNumber: 11; SheetTotal: 13; Project: STM32F769I-DISCO
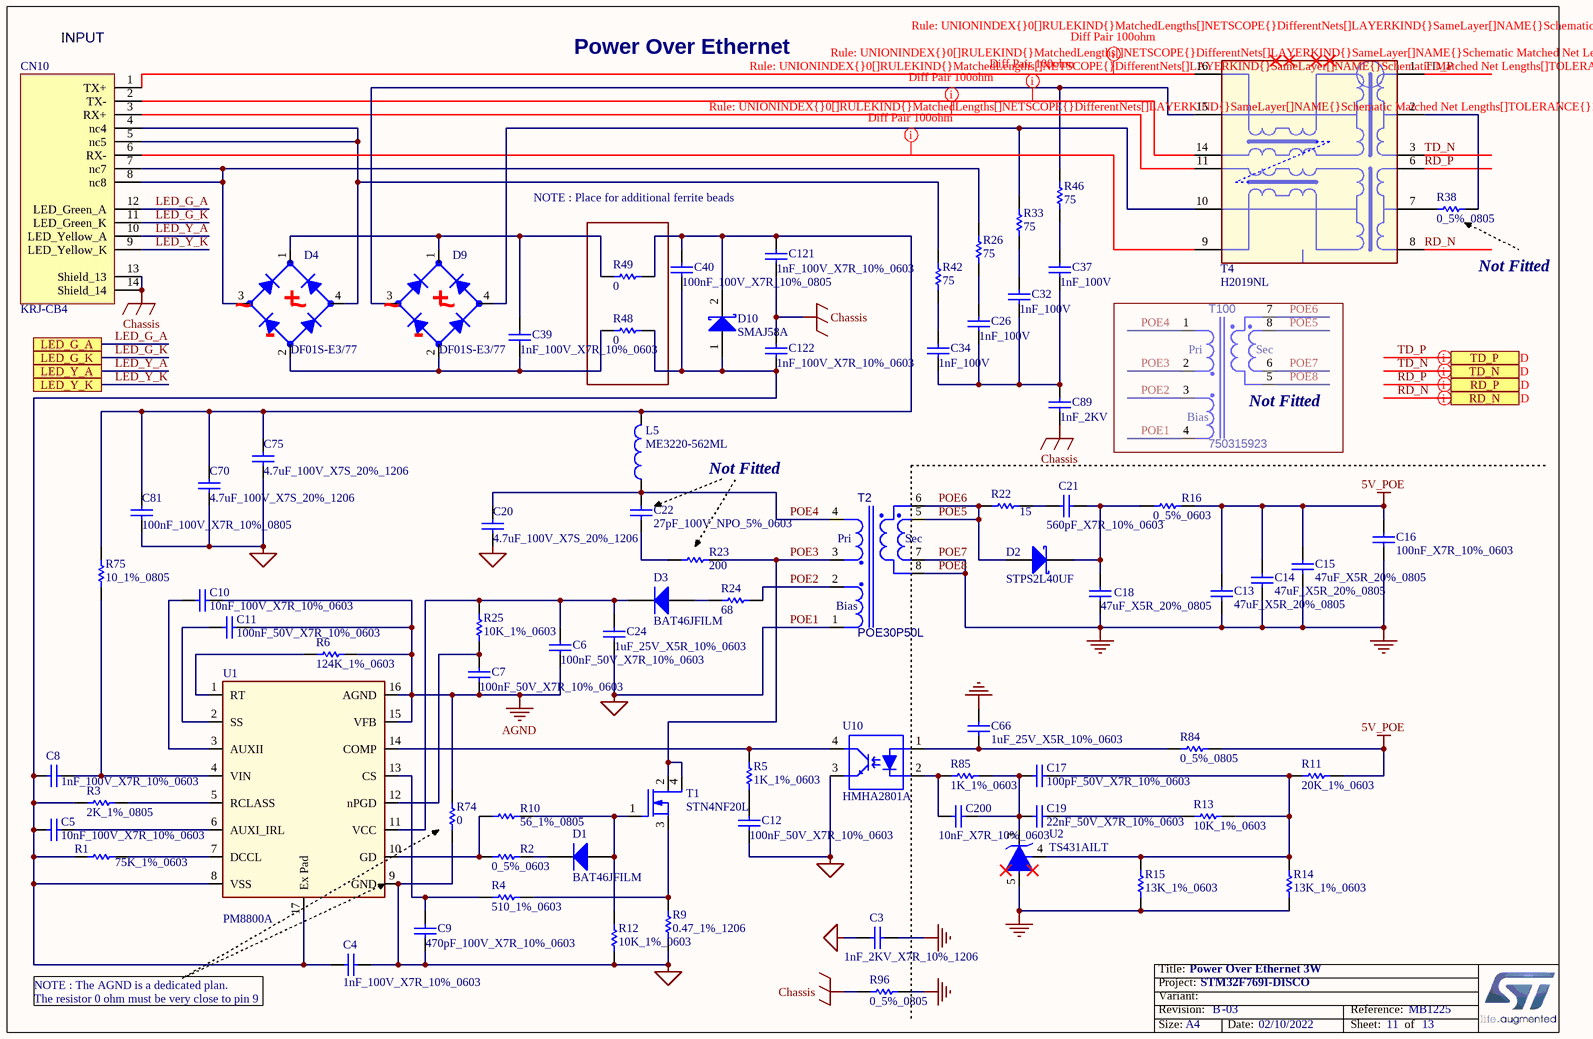
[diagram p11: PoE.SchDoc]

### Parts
C3  1nF_2KV_X7R_10%_1206  [1206C]
C4  1nF_100V_X7R_10%_0603  [0603C]
C5  10nF_100V_X7R_10%_0603  [0603C]
C6  100nF_50V_X7R_10%_0603  [0603C]
C7  100nF_50V_X7R_10%_0603  [0603C]
C8  1nF_100V_X7R_10%_0603  [0603C]
C9  470pF_100V_X7R_10%_0603  [0603C]
C10  10nF_100V_X7R_10%_0603  [0603C]
C11  100nF_50V_X7R_10%_0603  [0603C]
C12  100nF_50V_X7R_10%_0603  [0603C]
C13  47uF_X5R_20%_0805  [0805C]
C14  47uF_X5R_20%_0805  [0805C]
C15  47uF_X5R_20%_0805  [0805C]
C16  100nF_X7R_10%_0603  [0603C]
C17  100pF_50V_X7R_10%_0603  [0603C]
C18  47uF_X5R_20%_0805  [0805C]
C19  22nF_50V_X7R_10%_0603  [0603C]
C20  4.7uF_100V_X7S_20%_1206  [1206C]
C21  560pF_X7R_10%_0603  [0603C]
C22  27pF_100V_NPO_5%_0603  [0603C]
C24  1uF_25V_X5R_10%_0603  [0603C]
C26  1nF_100V  [0603C]
C32  1nF_100V  [0603C]
C34  1nF_100V  [0603C]
C37  1nF_100V  [0603C]
C39  1nF_100V_X7R_10%_0603  [0603C]
C40  100nF_100V_X7R_10%_0805  [0805C]
C66  1uF_25V_X5R_10%_0603  [0603C]
C70  4.7uF_100V_X7S_20%_1206  [1206C]
C75  4.7uF_100V_X7S_20%_1206  [1206C]
C81  100nF_100V_X7R_10%_0805  [0805C]
C89  1nF_2KV  [1206C]
C121  1nF_100V_X7R_10%_0603  [0603C]
C122  1nF_100V_X7R_10%_0603  [0603C]
C200  10nF_X7R_10%_0603  [0603C]
CN10  KRJ-CB4  [RJ45_LED_KRJ-CB4R2GYZNL_EM]
D1  BAT46JFILM  [SOD-323]
D2  STPS2L40UF  [SMB]
D3  BAT46JFILM  [SOD-323]
D4  DF01S-E3/77  [DBS101-107G]
D9  DF01S-E3/77  [DBS101-107G]
D10  SMAJ58A  [SMA]
L5  ME3220-562ML  [LSM2_3R2X2R8_H2]
R1  75K_1%_0603  [0603R]
R2  0_5%_0603  [0603R-GS]
R3  2K_1%_0805  [0805R]
R4  510_1%_0603  [0603R]
R5  1K_1%_0603  [0603R]
R6  124K_1%_0603  [0603R]
R9  0.47_1%_1206  [1206R]
R10  56_1%_0805  [0805R]
R11  20K_1%_0603  [0603R]
R12  10K_1%_0603  [0603R]
R13  10K_1%_0603  [0603R]
R14  13K_1%_0603  [0603R]
R15  13K_1%_0603  [0603R]
R16  0_5%_0603  [0603R-GS]
R22  15  [0805R]
R23  200  [1206R]
R24  68  [0805R]
R25  10K_1%_0603  [0603R]
R26  75  [0805R]
R33  75  [0805R]
R38  0_5%_0805  [0805R]
R42  75  [0805R]
R46  75  [0805R]
R48  0  [0805R]
R49  0  [0805R]
R74  0  [0603R-GS]
R75  10_1%_0805  [0805R]
R84  0_5%_0805  [0805R]
R85  1K_1%_0603  [0603R]
R96  0_5%_0805  [0805R]
T1  STN4NF20L  [SOT-223]
T2  POE30P50L  [TF_10R9X13R2-12R2X14R4_CPT]
T4  H2019NL  [TF_16SM_12R7X9R65]
T100  750315923  [TF_8SM_12R04X12R85]
U1  PM8800A  [TSSOP16_0R65_5x6R4_TP]
U2  TS431AILT  [SOT23-5]
U10  HMHA2801A  [PC_4SM_1R27_2R5X6R8]

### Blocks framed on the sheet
Not Fitted: T100

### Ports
LED_G_A, LED_G_K, LED_Y_A, LED_Y_K, RD_N, RD_P, TD_N, TD_P

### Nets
5V_POE: C13.2 C14.2 C15.2 C16.2 R11.2 R16.2 R84.2
AGND: C6.1 C7.1 C10.2 C11.2 R6.2 R74.2 U1.15(VFB) U1.16(AGND)
Chassis: C89.1 C121.1 C122.2 CN10.13(Shield_13) CN10.14(Shield_14) R96.1
POE1: C3.1 C4.2 C9.1 C12.1 C20.1 C24.1 C70.1 C75.1 C81.1 R9.1 R12.1 R74.1 T2.1 T100.4 U1.9(GND) U10.3(Emitter)  [also labelled GND_POWER_IN]
POE7: C3.2 C13.1 C14.1 C15.1 C16.1 C18.1 C66.2 R14.1 R15.1 R96.2 T2.7 T2.8 T100.5 T100.6 U2.5(A)  [also labelled GND, POE8]
LED_G_A: CN10.12(LED_Green_A) ; port LED_G_A
LED_G_K: CN10.11(LED_Green_K) ; port LED_G_K
LED_Y_A: CN10.10(LED_Yellow_A) ; port LED_Y_A
LED_Y_K: CN10.9(LED_Yellow_K) ; port LED_Y_K
POE2: R24.2 T2.2 T100.3
POE3: R23.2 T1.2(D) T1.4(D) T2.3 T100.2
POE4: C20.2 C22.2 L5.1 T2.4 T100.1
POE5: D2.1(A) R22.1 T2.5 T2.6 T100.7 T100.8  [also labelled POE6]
RD_N: T4.8(rd-) ; port RD_N
RD_P: T4.6(rd+) ; port RD_P
TD_N: T4.3(td-) ; port TD_N
TD_P: T4.1(td+) ; port TD_P
NetC4_1: C4.1 C5.1 C8.1 C40.1 C122.1 D10.1(A) R1.1 R3.1 R48.2 U1.8(VSS) U1.17(Ex_Pad)
NetC5_2: C5.2 U1.6(AUXI_IRL)
NetC6_2: C6.2 C24.2 D3.2(K) R25.2 U1.11(VCC)
NetC7_2: C7.2 R25.1 U1.12(nPGD)
NetC8_2: C8.2 R75.1 U1.4(VIN)
NetC9_2: C9.2 R4.1 U1.13(CS)
NetC10_1: C10.1 U1.3(AUXII)
NetC11_1: C11.1 U1.2(SS)
NetC12_2: C12.2 R5.1
NetC17_1: C17.1 C19.1 C200.2 R85.2 U2.3(K)
NetC17_2: C17.2 R11.1 R13.2 R14.2 R15.2 U2.4(REF)
NetC18_2: C18.2 C21.2 D2.2(K) R16.1
NetC19_2: C19.2 R13.1
NetC21_1: C21.1 R22.2
NetC22_1: C22.1 R23.1
NetC26_1: C26.1 C32.1 C34.1 C37.1 C89.2
NetC26_2: C26.2 R26.1
NetC32_2: C32.2 R33.1
NetC34_2: C34.2 R42.1
NetC37_2: C37.2 R46.1
NetC39_1: C39.1 D4.2(DC_OUT_MINUS) D9.2(DC_OUT_MINUS) R48.1
NetC39_2: C39.2 D4.1(DC_OUT_PLUS) D9.1(DC_OUT_PLUS) R49.1
NetC40_2: C40.2 C70.2 C75.2 C81.2 C121.2 D10.2(K) L5.2 R49.2 R75.2
NetC66_1: C66.1 R84.1 U10.1(Anode)
NetC200_1: C200.1 R85.1 U10.2(B)
NetCN10_1: CN10.1(TX+) T4.16(tx1+)
NetCN10_2: CN10.2(TX-) T4.14(tx1-)
NetCN10_3: CN10.3(RX+) T4.11(rx1+)
NetCN10_4: CN10.4(nc4) CN10.5(nc5) D4.4(AC_IN_1) R42.2
NetCN10_6: CN10.6(RX-) T4.9(rx-)
NetCN10_7: CN10.7(nc7) CN10.8(nc8) D4.3(AC_IN_2) R26.2
NetD1_1: D1.1(A) R10.2 R12.2 T1.1(G)
NetD1_2: D1.2(K) R2.2
NetD3_1: D3.1(A) R24.1
NetD9_3: D9.3(AC_IN_2) R46.2 T4.15(txct)
NetD9_4: D9.4(AC_IN_1) R33.2 T4.10(rxct)
NetR1_2: R1.2 U1.7(DCCL)
NetR2_1: R2.1 R10.1 U1.10(GD)
NetR3_2: R3.2 U1.5(RCLASS)
NetR4_2: R4.2 R9.2 T1.3(S)
NetR5_2: R5.2 U1.14(COMP) U10.4(Collector)
NetR6_1: R6.1 U1.1(RT)
NetR38_1: R38.1 T4.7(rct)
NetR38_2: R38.2 T4.2(tct)

Not connected (* = marked no-connect by the designer): T4 4(nc_4)* 5(nc_5)* 12(nc_12)* 13(nc_13)*; U2 1(nc_1)* 2(nc_2)*

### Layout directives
differential pair: RD_N, RD_P, TD_N, TD_P
rule Matched Net Lengths [Tolerance = 100mil]: NetCN10_1, NetCN10_2, NetCN10_3, NetCN10_6

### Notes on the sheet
- (near CN10) INPUT
- Power Over Ethernet
- NOTE : Place for additional ferrite beads
- (near R38) Not Fitted
- Not Fitted
- NOTE : The AGND is a dedicated plan.
  The resistor 0 ohm must be very close to pin 9

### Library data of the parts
C3 C89 = Cap_1nF_2KV_X7R_10%_1206: Capacitor,1nF,2KV,X7R,10%,1206,YAGEO; Order: CC1206KKX7RDBB102
C4 C8 C26 C32 C34 C37 C39 C121 C122 = Cap_1nF_100V_X7R_10%_0603: Capacitor,1nF,100V,X7R,10%,0603,YAGEO; Order: CC0603KRX7R0BB102
C5 C10 = Cap_10nF_100V_X7R_10%_0603: Capacitor,10nF,100V,X7R,10%,0603,YAGEO; Manuf_Part_1: CC0603KRX7R0BB103
C6 C7 C11 C12 = Cap_100nF_50V_X7R_10%_0603: Capacitor,100nF,50V,X7R,10%,0603,YAGEO; Manuf_Part_1: CC0603KRX7R9BB104
C9 = Cap_470pF_100V_X7R_10%_0603: Capacitor,470pF,100V,X7R,10%,0603,AVX; Manuf_Part_1: 06031C471KAT2A
C13-C15 C18 = Cap_47uF_X5R_20%_0805: Capacitor,47uF,10V,X5R,20%,0805,MURATA; Manuf_Part_1: GRM21BR61A476ME15K; Order: GRM21BR61A476ME15K-ND
C16 = Cap_100nF_X7R_10%_0603: Capacitor,100nF,16V,X7R,10%,0603,YAGEO; Manuf_Part_1: CC0603KRX7R9BB104
C17 = Cap_100pF_50V_X7R_10%_0603: Capacitor,100pF,50V,X7R,10%,0603,AVX; Manuf_Part_1: 06035C101JAT4A
C19 = Cap_22nF_50V_X7R_10%_0603: Capacitor,22nF,50V,X7R,10%,0603,YAGEO; Manuf_Part_1: CC0603KRX7R9BB223
C20 C70 C75 = Cap_4.7uF_100V_X7S_20%_1206: Capacitor,4.7uF,100V, X7S,20%,1206,AVX; Manuf_Part_1: 12061Z475MAT2A
C21 = Cap_560pF_X7R_10%_0603: Capacitor,560pF,16V,X7R,10%,0603,AVX; Manuf_Part_1: 0603YC561KAT2A
C22 = Cap_27pF_100V_NPO_5%_0603: Capacitor,27pF,100V,NPO,5%,0603,YAGEO; Manuf_Part_1: CC0603JRNPO0BN270; Manuf_2: AVX; Manuf_Part_2: 06031A270JAT2A; Fitted: NO
C24 C66 = Cap_1uF_25V_X5R_10%_0603: Capacitor,1uF,25V,X5R,10%,0603,YAGEO; Manuf_Part_1: CC0603KRX5R8BB105
C40 C81 = Cap_100nF_100V_X7R_10%_0805: Capacitor,100nF,100V,X7R,10%,0805,TDK; Order: C2012X7R2A104K125AA
C200 = Cap_10nF_X7R_10%_0603: Capacitor,10nF,50V,X7R,10%,0603,YAGEO; Manuf_Part_1: CC0603KRX7R9BB103
CN10 = KRJ-CB4: 100 Base-TX (Fast Ethernet)  RJ45 single port (1x1) with LEDS Integrated Connector; Manuf_1: DGKYD; Manuf_Part_1: KRJ-CB4.2GYZNL
D1 D3 = BAT46JFILM: Schottky Single diode(150mA, 100V); Manuf_1: STM; Provided: ST; ECCN_US/EU: EAR99/NEC; Ref St: 9151125
D2 = STPS2L40UF: Low drop power Schottky rectifier(2A, 40V, 0.34V); Manuf_1: STM; Order: STPS2L40AF; Provided: ST; ECCN_US/EU: EAR99/NEC; Code - JEDEC: ******; Note: SMB footprint will accept STPS2L40U/UF/AF; Ref St: 9151009
D4 D9 = DF01S_SMD: Surface Mount Bridge Rectifiers; Manuf_1: VISHAY; Manuf_2: DIODES; Manuf_3: FAIRCHILD; Disrib: Sub Co
D10 = SMAJ58A: Transil 400W, VRM=58V; Manuf_1: STM; Manuf_Part_1: SMAJ58A-TR; ECCN_US/EU: EAR99/NEC; Provided: ST; Ref St: 9151124
L5 = ME3220-562ML: Power Inductor, 5.6uH, 0.2R, ME3220-562ML, CoilCraft; Manuf_2: Cyntec; Manuf_Part_2: SDET32251E-5R6MS-11
R1 = Res_75K_1%_0603: Resistor,75K,0603,1%,YAGEO; Manuf_Part_1: RC0603FR-0775KL
R2 R16 = Res_0_5%_0603: Resistor,0,0603,5%,YAGEO; Manuf_Part_1: RC0603JR-070RL; Value: 0; Order: 2363481
R3 = Res_2K_1%_0805: Resistor,2K,0805,1%,YAGEO; Manuf_Part_1: RC0805FR-072KL; Manuf_Part_2: RT0805FRE072KL
R4 = Res_510_1%_0603: Resistor,510,0603,1%,YAGEO; Manuf_Part_1: RC0603FR-07510RL; Value: 510
R5 R85 = Res_1K_1%_0603: Resistor,1K,0603,1%,YAGEO; Manuf_Part_1: RC0603FR-071KL
R6 = Res_124K_1%_0603: Resistor,124K,0603,1%,YAGEO; Manuf_Part_1: RC0603FR-07124KL
R9 = Res_0.47_1%_1206: Resistor,0.47,1206,1%,YAGEO; Manuf_Part_1: RL1206FR-070R47L; Manuf_Part_2: LTR18EZPFLR470; Manuf_2: Rohm Semiconductor; Value: 0.47
R10 = Res_56_1%_0805: Resistor,56,0805,1%,YAGEO; Manuf_Part_1: RC0805FR-0756RL; Value: 56; Order: 311-56.0CRTR-ND
R11 = Res_20K_1%_0603: Resistor,20K,0603,1%,YAGEO; Manuf_Part_1: RC0603FR-0720KL
R12 R13 R25 = Res_10K_1%_0603: Resistor,10K,0603,1%,YAGEO; Manuf_Part_1: RC0603FR-0710KL
R14 R15 = Res_13K_1%_0603: Resistor,13K,0603,1%,YAGEO; Manuf_Part_1: RC0603FR-0713KL
R22 = Res_15_1%_0805: Resistor,15,0805,1%,YAGEO; Manuf_Part_1: RC0805FR-0715RL
R23 = Res_200_1%_1206: Resistor,200,1206,1%,Rohm; Manuf_Part_1: LTR18EZPF2000; Manuf_1: Rohm Semiconductor; Fitted: NO
R24 = Res_68_1%_0805: Resistor,68,0805,1%,YAGEO; Manuf_Part_1: RC0805FR-0768RL
R26 R33 R42 R46 = Res_75_1%_0805: Resistor,75,0805,1%,YAGEO; Manuf_Part_1: RC0805FR-0775RL; Order: 311-75.0CRTR-ND
R38 = Res_0_5%_0805: Resistor,0,0805,5%,YAGEO; Manuf_Part_1: RC0805JR-070RL; Value: 0; Order: 2363489; Fitted: NO
R48 R49 = Res_0_5%_0805: Resistor,0,0805,5%,YAGEO; Manuf_Part_1: RC0805JR-070RL; Order: 2363489
R74 = Res_0_5%_0603: as R109 on sheet STM32F7
R75 = Res_10_1%_0805: Resistor,10,0805,1%,Stackpole,1/4W; Manuf_Part_1: RNCP0805FTD10R0; Manuf_1: Stackpole Electronics Inc; Value: 10
R84 R96 = Res_0_5%_0805: Resistor,0,0805,5%,YAGEO; Manuf_Part_1: RC0805JR-070RL; Value: 0; Order: 2363489
T1 = STN4NF20L: N-channel 200 V, 1.1ohm, 1 A, low gate charge STripFET II, Power MOSFET; Manuf_2: Fairchild; Manuf_Part_2: FDN86246; Manuf_1: ST; ECCN_US/EU: EAR99/NEC; Ref St: 9153018
T2 = POE30P_C: Flyback Transformers for 3 Watt, PoE applications, CoilCraft Cyntec; Manuf_Part_1: POEP30P50L; Manuf_Part_2: 86H-15181; Provided: Sub Co; Note: for Cyntec, Secondary 6, 7 removed
T4 = H2019: 10/100BASE-TX VoIP Magnetics Modules, Data Transformer; Manuf_Part_2: TLA-6T127LF, with different pinout; Manuf_1: PULSE; Manuf_2: TDK; Manuf_Part_3: KMS-1102NL; Manuf_3: DGKYD; Double foot print: TLA-6T127LF, pin 10, 12, 13, 15 differents; ECCN_US/EU: EAR99/NEC
T100 = POE30P_W: Flyback Transformers for 3 Watt, PoE applications, Wurth; Provided: Sub Co; Note: Compatible with CoilCraft but swap pins 1 and 4, pins 2 and 3, pins 5 and 8, pins 6 and 7; Fitted: NO
U1 = PM8800A: Integrated IEEE 802.3af compliant PoE-PD interface, and PWM controller with support of external source; Manuf_Part_1: PM8800ATR; Manuf_1: ST; Provided: STM; ECCN_US/EU: EAR99/NEC; Ref St: 9177966
U2 = TS431AILT: Low voltage adjustable shunt reference; Manuf_1: ST; ECCN_US/EU: EAER99/NEC; Ref St: 9177032
U10 = HMHA2801A: OPTOISOLATOR 3.7KV TRANSISTOR 4SMD; Manuf_1: FAIRCHILD; Order: HMHA2801A-ND; ECCN_US/EU: EAR99/NEC

## Sheet DSI_LCD.SchDoc: MIPI connector for DSI LCD and HDMI boards.
size A4; Date: 29-OCT-2015; Author: A.B; CompanyName: STMicroelectronics; Organization: MCD/TOOLS/GNB; Address1: 12, Rue Jules HOROWITZ; Address2: 38019 Grenoble; Address3: FRANCE; DocumentNumber: MB1225; Revision: B-01; SheetNumber: 12; SheetTotal: 13; Project: STM32F769I-DISCO
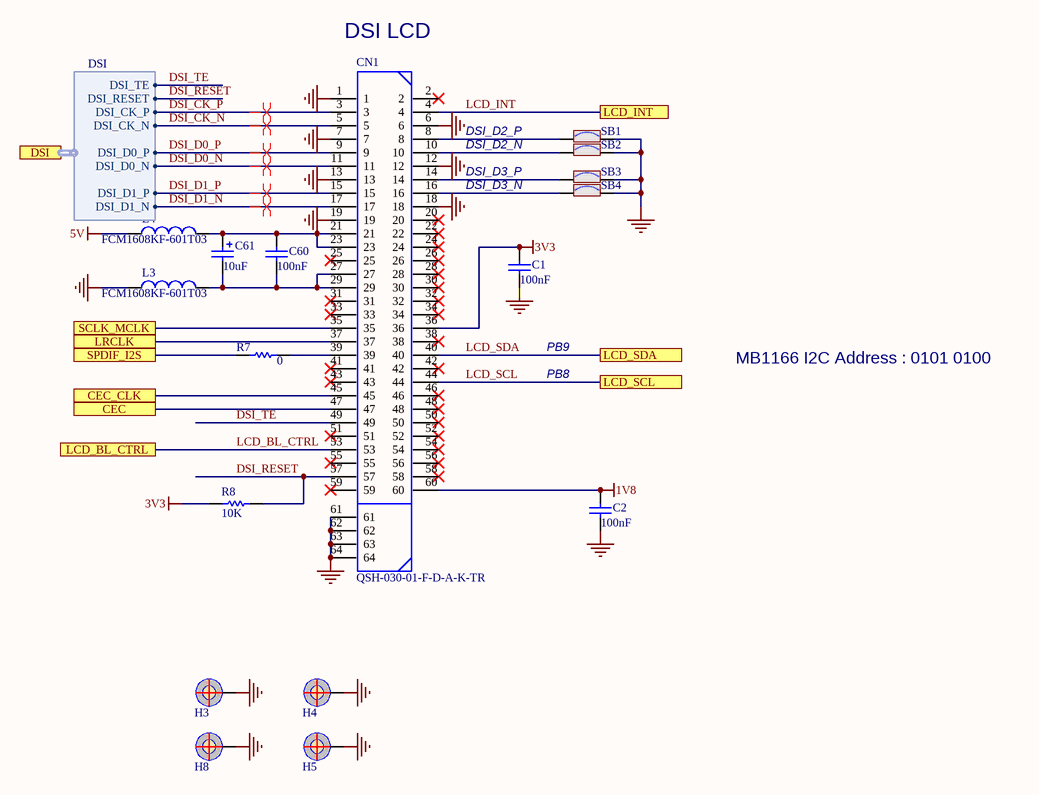
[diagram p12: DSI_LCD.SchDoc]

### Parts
C1  100nF  [0603C]
C2  100nF  [0603C]
C60  100nF  [0603C]
C61  10uF  [TAN-A]
CN1  QSH-030-01-F-D-A-K-TR  [QSH-030-01-F-D-A]
H3  POSITION HOLE  [HOLE_C9D4R5-1]  (value not drawn)
H4  POSITION HOLE  [HOLE_C9D4R5]  (value not drawn)
H5  POSITION HOLE  [HOLE_C9D4R5]  (value not drawn)
H8  POSITION HOLE  [HOLE_C9D4R5-1]  (value not drawn)
L3  FCM1608KF-601T03  [0603L]
L4  FCM1608KF-601T03  [0603L]
R7  0  [0402R]
R8  10K  [0402R]
SB1  Solder Bridge ON  [JP2_SMD]  (value not drawn)
SB2  Solder Bridge ON  [JP2_SMD]  (value not drawn)
SB3  Solder Bridge ON  [JP2_SMD]  (value not drawn)
SB4  Solder Bridge ON  [JP2_SMD]  (value not drawn)

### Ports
CEC, CEC_CLK, DSI (harness DSI), LCD_BL_CTRL, LCD_INT, LCD_SCL, LCD_SDA, LRCLK, SCLK_MCLK, SPDIF_I2S

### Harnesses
DSI: DSI_CK_P, DSI_CK_N, DSI_D0_P, DSI_D0_N, DSI_D1_P, DSI_D1_N, DSI_TE, DSI_RESET

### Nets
1V8: C2.2 CN1.60
3V3: C1.2 CN1.36 R8.1
5V: L4.1
GND: C1.1 C2.1 CN1.1 CN1.6 CN1.7 CN1.12 CN1.13 CN1.18 CN1.19 CN1.61 CN1.62 CN1.63 CN1.64 H3.1 H4.1 H5.1 H8.1 L3.1 SB1.2 SB2.2 SB3.2 SB4.2  [project net POE7]
CEC: CN1.47 ; port CEC
CEC_CLK: CN1.45 ; port CEC_CLK
DSI_CK_N: CN1.5 ; port DSI.DSI_CK_N
DSI_CK_P: CN1.3 ; port DSI.DSI_CK_P
DSI_D0_N: CN1.11 ; port DSI.DSI_D0_N
DSI_D0_P: CN1.9 ; port DSI.DSI_D0_P
DSI_D1_N: CN1.17 ; port DSI.DSI_D1_N
DSI_D1_P: CN1.15 ; port DSI.DSI_D1_P
DSI_RESET: CN1.57 R8.2 ; port DSI.DSI_RESET
DSI_TE: CN1.49 ; port DSI.DSI_TE
LCD_BL_CTRL: CN1.53 ; port LCD_BL_CTRL
LCD_INT: CN1.4 ; port LCD_INT
LCD_SCL: CN1.44 ; port LCD_SCL  [project net AUDIO_SCL]
LCD_SDA: CN1.40 ; port LCD_SDA  [project net AUDIO_SDA]
LRCLK: CN1.37 ; port LRCLK
PD11: R7.1 ; port SPDIF_I2S
SCLK_MCLK: CN1.35 ; port SCLK_MCLK
NetC60_1: C60.1 C61.2 CN1.27 CN1.29 L3.2
NetC60_2: C60.2 C61.1 CN1.21 CN1.23 L4.2
NetCN1_8: CN1.8 SB1.1
NetCN1_10: CN1.10 SB2.1
NetCN1_14: CN1.14 SB3.1
NetCN1_16: CN1.16 SB4.1
NetCN1_39: CN1.39 R7.2

Not connected (* = marked no-connect by the designer): CN1 2* 20* 22* 24* 25* 26* 28* 30* 31* 32* 33* 34* 38* 41* 42* 43* 46* 48* 50* 51* 52* 54* 55* 56* 58* 59*

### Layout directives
differential pair: DSI_CK_N, DSI_CK_P, DSI_D0_N, DSI_D0_P, DSI_D1_N, DSI_D1_P

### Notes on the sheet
- DSI LCD
- DSI_D2_P
- DSI_D2_N
- DSI_D3_P
- DSI_D3_N
- PB9
- PB8
- MB1166 I2C Address : 0101 0100

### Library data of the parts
C1 C2 C60 = Cap_100nF_X7R_10%_0603: as C16 on sheet PoE
C61 = Cap_10uF_POL_10%_TANA: as C36 on sheet Ethernet
CN1 = QSH-030-01-F-D-A: HIGH SPEED SOCKET STRIP, .5mm PITCH, 60 PINS; Manuf_1: SAMTEC; Provided: Sub Co; Ref St: 9183715
L3 L4 = BEAD_600R_350MA_0603: as L6 on sheet STM32F7
R7 = Res_0_5%_0402: as R129 on sheet USB_OTG_HS
R8 = Res_10K_1%_0402: as R134 on sheet USB_OTG_HS
SB1-SB4 = SB_ON: Solder: YES

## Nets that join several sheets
1V8: ST_LINK_V2-1 (C100.2 U14.2 U14.4), AUDIO (6 pins), USB_OTG_HS (C145.2 U20.28 U20.30), DSI_LCD (C2.2 CN1.60)
3V3: ST_LINK_V2-1 (C48.2 C49.2 U7.4 U14.3), AUDIO (24 pins), Peripherals (16 pins), QSPI (C96.2 R86.2 U12.8 U250.8), Arduino_ Connectors (CN11.2 CN11.4), SDRAM (28 pins), USB_OTG_HS (11 pins), STM32F7 (12 pins), Ethernet (13 pins), DSI_LCD (C1.2 CN1.36 R8.1)
5V: ST_LINK_V2-1 (11 pins), Arduino_ Connectors (CN11.5), USB_OTG_HS (C150.1 U20.21 U21.5), DSI_LCD (L4.1)
5V_POE: ST_LINK_V2-1 (CN3.7 D6.1), PoE (7 pins)
5V_USB_HS: ST_LINK_V2-1 (CN3.3 D8.1), USB_OTG_HS (CN15.1 D12.A1 L7.2)
E5V: ST_LINK_V2-1 (6 pins), Arduino_ Connectors (R103.2)
POE7: TOP (H1.1 H2.1 H6.1 H7.1), ST_LINK_V2-1 (52 pins), AUDIO (55 pins), Peripherals (11 pins), QSPI (C96.1 U12.4 U250.4), Arduino_ Connectors (5 pins), SDRAM (28 pins), USB_OTG_HS (25 pins), STM32F7 (58 pins), Ethernet (14 pins), PoE (15 pins), DSI_LCD (22 pins)
VIN: ST_LINK_V2-1 (C129.2 U18.3), Arduino_ Connectors (CN11.8)
VREF+: Arduino_ Connectors (C85.2 R98.2), STM32F7 (C101.1 C102.2 R110.2 U13.P1)
ARD_A0: Arduino_ Connectors (CN14.1), STM32F7 (U13.P3)
ARD_A1: Arduino_ Connectors (CN14.2), STM32F7 (U13.N4)
ARD_A2: Arduino_ Connectors (CN14.3), STM32F7 (U13.M4)
ARD_A3: Arduino_ Connectors (CN14.4), STM32F7 (U13.L1)
ARD_A4: Arduino_ Connectors (SB14.1), STM32F7 (U13.L3)
ARD_A5: Arduino_ Connectors (SB12.1), STM32F7 (U13.L2)
ARD_D0: Arduino_ Connectors (CN13.1), STM32F7 (U13.G15)
ARD_D1: Arduino_ Connectors (CN13.2), STM32F7 (U13.H15)
ARD_D2: Arduino_ Connectors (CN13.3), STM32F7 (U13.R7)
ARD_D3: Arduino_ Connectors (CN13.4), STM32F7 (U13.K2)
ARD_D4: Arduino_ Connectors (CN13.5), STM32F7 (U13.R6)
ARD_D5: Arduino_ Connectors (CN13.6), STM32F7 (U13.G14)
ARD_D6: Arduino_ Connectors (CN13.7), STM32F7 (U13.K1)
ARD_D7: Arduino_ Connectors (CN13.8), STM32F7 (U13.N8)
ARD_D8: Arduino_ Connectors (CN9.1), STM32F7 (U13.M9)
ARD_D9: Arduino_ Connectors (CN9.2), STM32F7 (U13.P13)
ARD_D10: Arduino_ Connectors (CN9.3), STM32F7 (U13.C15)
ARD_D11: Arduino_ Connectors (CN9.4), STM32F7 (U13.R15)
ARD_D12: Arduino_ Connectors (CN9.5), STM32F7 (U13.R14)
ARD_D13: Arduino_ Connectors (CN9.6 SB15.2), STM32F7 (U13.B15)
ARD_D14: Arduino_ Connectors (CN9.9 SB13.1), STM32F7 (R89.2 U13.B4)
ARD_D15: Arduino_ Connectors (CN9.10 SB11.1), STM32F7 (R91.2 U13.A7)
Audio_INT: AUDIO (U11.G3), STM32F7 (U13.B10)
AUDIO_SCL: AUDIO (R88.1), STM32F7 (R17.1 U13.M10), DSI_LCD (CN1.44)
AUDIO_SDA: AUDIO (R95.1), STM32F7 (R90.2 U13.B5), DSI_LCD (CN1.40)
B_USER: Peripherals (SB9.1), STM32F7 (U13.N3)
CEC: STM32F7 (U13.A13), DSI_LCD (CN1.47)
CEC_CLK: STM32F7 (TP2.1 U13.F15), DSI_LCD (CN1.45)
DFSDM_CKOUT: AUDIO (5 pins), STM32F7 (TP102.1 U13.C11)
DFSDM_DATIN1: AUDIO (TP103.1 U5.4 U6.4), STM32F7 (TP101.1 U13.L4)
DFSDM_DATIN5: AUDIO (TP104.1 U8.4 U9.4), STM32F7 (TP100.1 U13.B13)
DSI_CK_N: STM32F7 (U13.H13), DSI_LCD (CN1.5)
DSI_CK_P: STM32F7 (U13.H12), DSI_LCD (CN1.3)
DSI_D0_N: STM32F7 (U13.J13), DSI_LCD (CN1.11)
DSI_D0_P: STM32F7 (U13.J12), DSI_LCD (CN1.9)
DSI_D1_N: STM32F7 (U13.F13), DSI_LCD (CN1.17)
DSI_D1_P: STM32F7 (U13.F12), DSI_LCD (CN1.15)
DSI_RESET: STM32F7 (U13.D10), DSI_LCD (CN1.57 R8.2)
DSI_TE: STM32F7 (U13.P7), DSI_LCD (CN1.49)
EXT_RST: Peripherals (CN2.6 R54.2), STM32F7 (U13.N13)
EXT_SCL: Peripherals (CN2.5 R56.2), STM32F7 (U13.M12)
EXT_SDA: Peripherals (R52.1 SB6.1), STM32F7 (U13.J15)
FMC_A0: SDRAM (U17.G8), STM32F7 (U13.D2)
FMC_A1: SDRAM (U17.G9), STM32F7 (U13.E2)
FMC_A2: SDRAM (U17.F7), STM32F7 (U13.G2)
FMC_A3: SDRAM (U17.F3), STM32F7 (U13.H2)
FMC_A4: SDRAM (U17.G1), STM32F7 (U13.J2)
FMC_A5: SDRAM (U17.G2), STM32F7 (U13.K3)
FMC_A6: SDRAM (U17.G3), STM32F7 (U13.M6)
FMC_A7: SDRAM (U17.H1), STM32F7 (U13.N6)
FMC_A8: SDRAM (U17.H2), STM32F7 (U13.P6)
FMC_A9: SDRAM (U17.J3), STM32F7 (U13.M8)
FMC_A10: SDRAM (U17.G7), STM32F7 (U13.N7)
FMC_A11: SDRAM (U17.H9), STM32F7 (U13.M7)
FMC_A12: SDRAM (U17.E3), STM32F7 (U13.M13)
FMC_BA0: SDRAM (U17.J7), STM32F7 (U13.N12)
FMC_BA1: SDRAM (U17.H8), STM32F7 (U13.N11)
FMC_D0: SDRAM (TP27.1 U17.R8), STM32F7 (U13.L12)
FMC_D1: SDRAM (U17.N7), STM32F7 (U13.K13)
FMC_D2: SDRAM (U17.R9), STM32F7 (U13.B12)
FMC_D3: SDRAM (U17.N8), STM32F7 (U13.C12)
FMC_D4: SDRAM (U17.P9), STM32F7 (U13.R8)
FMC_D5: SDRAM (U17.M8), STM32F7 (U13.N9)
FMC_D6: SDRAM (U17.M7), STM32F7 (U13.P9)
FMC_D7: SDRAM (U17.L8), STM32F7 (U13.R9)
FMC_D8: SDRAM (U17.L2), STM32F7 (U13.P10)
FMC_D9: SDRAM (U17.M3), STM32F7 (U13.R10)
FMC_D10: SDRAM (U17.M2), STM32F7 (U13.R12)
FMC_D11: SDRAM (U17.P1), STM32F7 (U13.P11)
FMC_D12: SDRAM (U17.N2), STM32F7 (U13.R11)
FMC_D13: SDRAM (U17.R1), STM32F7 (U13.L15)
FMC_D14: SDRAM (U17.N3), STM32F7 (U13.L14)
FMC_D15: SDRAM (U17.R2), STM32F7 (U13.K15)
FMC_D16: SDRAM (U17.E8), STM32F7 (U13.P14)
FMC_D17: SDRAM (U17.D7), STM32F7 (U13.N14)
FMC_D18: SDRAM (U17.D8), STM32F7 (U13.P15)
FMC_D19: SDRAM (U17.B9), STM32F7 (U13.N15)
FMC_D20: SDRAM (U17.C8), STM32F7 (U13.M15)
FMC_D21: SDRAM (U17.A9), STM32F7 (U13.E12)
FMC_D22: SDRAM (U17.C7), STM32F7 (U13.E13)
FMC_D23: SDRAM (U17.A8), STM32F7 (U13.D13)
FMC_D24: SDRAM (U17.A2), STM32F7 (U13.E14)
FMC_D25: SDRAM (U17.C3), STM32F7 (U13.D14)
FMC_D26: SDRAM (U17.A1), STM32F7 (U13.C14)
FMC_D27: SDRAM (U17.C2), STM32F7 (U13.C13)
FMC_D28: SDRAM (U17.B1), STM32F7 (U13.D6)
FMC_D29: SDRAM (U17.D2), STM32F7 (U13.D4)
FMC_D30: SDRAM (U17.D3), STM32F7 (U13.E4)
FMC_D31: SDRAM (U17.E2), STM32F7 (U13.D5)
FMC_NBL0: SDRAM (U17.K9), STM32F7 (U13.A6)
FMC_NBL1: SDRAM (U17.K1), STM32F7 (U13.A5)
FMC_NBL2: SDRAM (U17.F8), STM32F7 (U13.C3)
FMC_NBL3: SDRAM (U17.F2), STM32F7 (U13.D3)
FMC_SDCKE0: SDRAM (U17.J2), STM32F7 (U13.K4)
FMC_SDCLK: SDRAM (TP26.1 U17.J1), STM32F7 (U13.H14)
FMC_SDNCAS: SDRAM (U17.K7), STM32F7 (U13.B7)
FMC_SDNE0: SDRAM (U17.J8), STM32F7 (U13.J4)
FMC_SDNRAS: SDRAM (U17.J9), STM32F7 (U13.P8)
FMC_SDNWE: SDRAM (TP28.1 U17.K8), STM32F7 (U13.J3)
LCD_BL_CTRL: STM32F7 (U13.H3), DSI_LCD (CN1.53)
LCD_INT: STM32F7 (U13.G3), DSI_LCD (CN1.4)
LD_USER1: Peripherals (R62.1), STM32F7 (U13.B9)
LD_USER2: Peripherals (R63.1), STM32F7 (U13.M14)
LRCLK: STM32F7 (TP3.1), DSI_LCD (CN1.37)
NRST: ST_LINK_V2-1 (SB20.2), Peripherals (SB10.1), Arduino_ Connectors (CN11.3), USB_OTG_HS (U20.27), STM32F7 (R106.1 U13.J1), Ethernet (U3.15)
OSC_25M: STM32F7 (R104.1 X2.3), Ethernet (R27.1)
OTG_HS_OverCurrent: USB_OTG_HS (R129.2), STM32F7 (U13.D11)
PA1: STM32F7 (U13.N2), Ethernet (R45.1 U3.14)
PA2: STM32F7 (U13.P2), Ethernet (R47.1 U3.12)
PA3: USB_OTG_HS (U20.3), STM32F7 (U13.R2)
PA5: USB_OTG_HS (U20.1), STM32F7 (U13.P4)
PA7: STM32F7 (U13.R3), Ethernet (R44.2)
PA9: ST_LINK_V2-1 (JP5.1 SB18.1), STM32F7 (U13.E15)
PA10: ST_LINK_V2-1 (JP5.2 SB17.1), STM32F7 (U13.D15)
PA13: ST_LINK_V2-1 (SB22.2), STM32F7 (U13.A15)
PA14: ST_LINK_V2-1 (SB19.2), STM32F7 (U13.A14)
PB0: USB_OTG_HS (U20.4), STM32F7 (U13.R5)
PB1: USB_OTG_HS (U20.5), STM32F7 (U13.R4)
PB2: QSPI (U12.6 U250.6), STM32F7 (U13.M5)
PB4: Peripherals (CN5.2 R82.1), STM32F7 (U13.A9)
PB5: USB_OTG_HS (U20.13), STM32F7 (U13.A8)
PB6: QSPI (R86.1 U12.1 U250.1), STM32F7 (U13.B6)
PB10: USB_OTG_HS (U20.6), STM32F7 (U13.P12)
PB11: USB_OTG_HS (U20.7), STM32F7 (U13.R13)
PB12: USB_OTG_HS (U20.9), STM32F7 (U13.L13)
PB13: USB_OTG_HS (U20.10), STM32F7 (U13.K14)
PC0: USB_OTG_HS (U20.29), STM32F7 (U13.M2)
PC1: STM32F7 (U13.M3), Ethernet (U3.13)
PC4: STM32F7 (U13.N5), Ethernet (R36.2)
PC5: STM32F7 (U13.P5), Ethernet (R32.2)
PC9: QSPI (U12.5 U250.5), STM32F7 (U13.F14)
PC10: QSPI (U12.2 U250.2), STM32F7 (U13.B14)
PC12: Peripherals (R50.1), STM32F7 (U13.A12)
PD2: Peripherals (R57.2), STM32F7 (U13.D12)
PD5: STM32F7 (U13.C10), Ethernet (R40.2 U3.10)
PD6: Peripherals (CN5.5), STM32F7 (U13.B11)
PD7: Peripherals (CN5.3 R81.1), STM32F7 (U13.A11)
PD11: AUDIO (R100.1 TP20.1), STM32F7 (U13.N10), DSI_LCD (R7.1)
PD13: QSPI (U12.7 U250.7), STM32F7 (U13.M11)
PE2: QSPI (U12.3 U250.3), STM32F7 (U13.A3)
PE3: AUDIO (U11.F2), STM32F7 (TP11.1 U13.A2)
PE4: AUDIO (U11.E3), STM32F7 (TP6.1 U13.A1)
PE5: AUDIO (U11.G1), STM32F7 (TP8.1 U13.B1)
PE6: AUDIO (U11.E4), STM32F7 (TP7.1 U13.B2)
PG7: AUDIO (U11.D3), STM32F7 (TP22.1 U13.J14)
PG9: Peripherals (CN5.7 R80.1), STM32F7 (U13.D9)
PG10: Peripherals (CN5.8 R79.1), STM32F7 (U13.C8)
PG11: STM32F7 (U13.B8), Ethernet (U3.16)
PG12: AUDIO (R112.2 R114.2 U15.4), STM32F7 (U13.C7)
PG13: STM32F7 (U13.B3), Ethernet (U3.17)
PG14: STM32F7 (U13.A4), Ethernet (U3.18)
PH4: USB_OTG_HS (U20.2), STM32F7 (U13.H4)
PI11: USB_OTG_HS (U20.31), STM32F7 (U13.F3)
PI15: Peripherals (R73.1 R76.1), STM32F7 (U13.G4)
PJ14: Peripherals (CN2.4 R200.2), STM32F7 (U13.C9)
SCLK_MCLK: STM32F7 (TP1.1), DSI_LCD (CN1.35)
SWO: ST_LINK_V2-1 (SB21.2), STM32F7 (R92.1)
uSD_D2: Peripherals (CN5.1 R83.1), STM32F7 (R93.1)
